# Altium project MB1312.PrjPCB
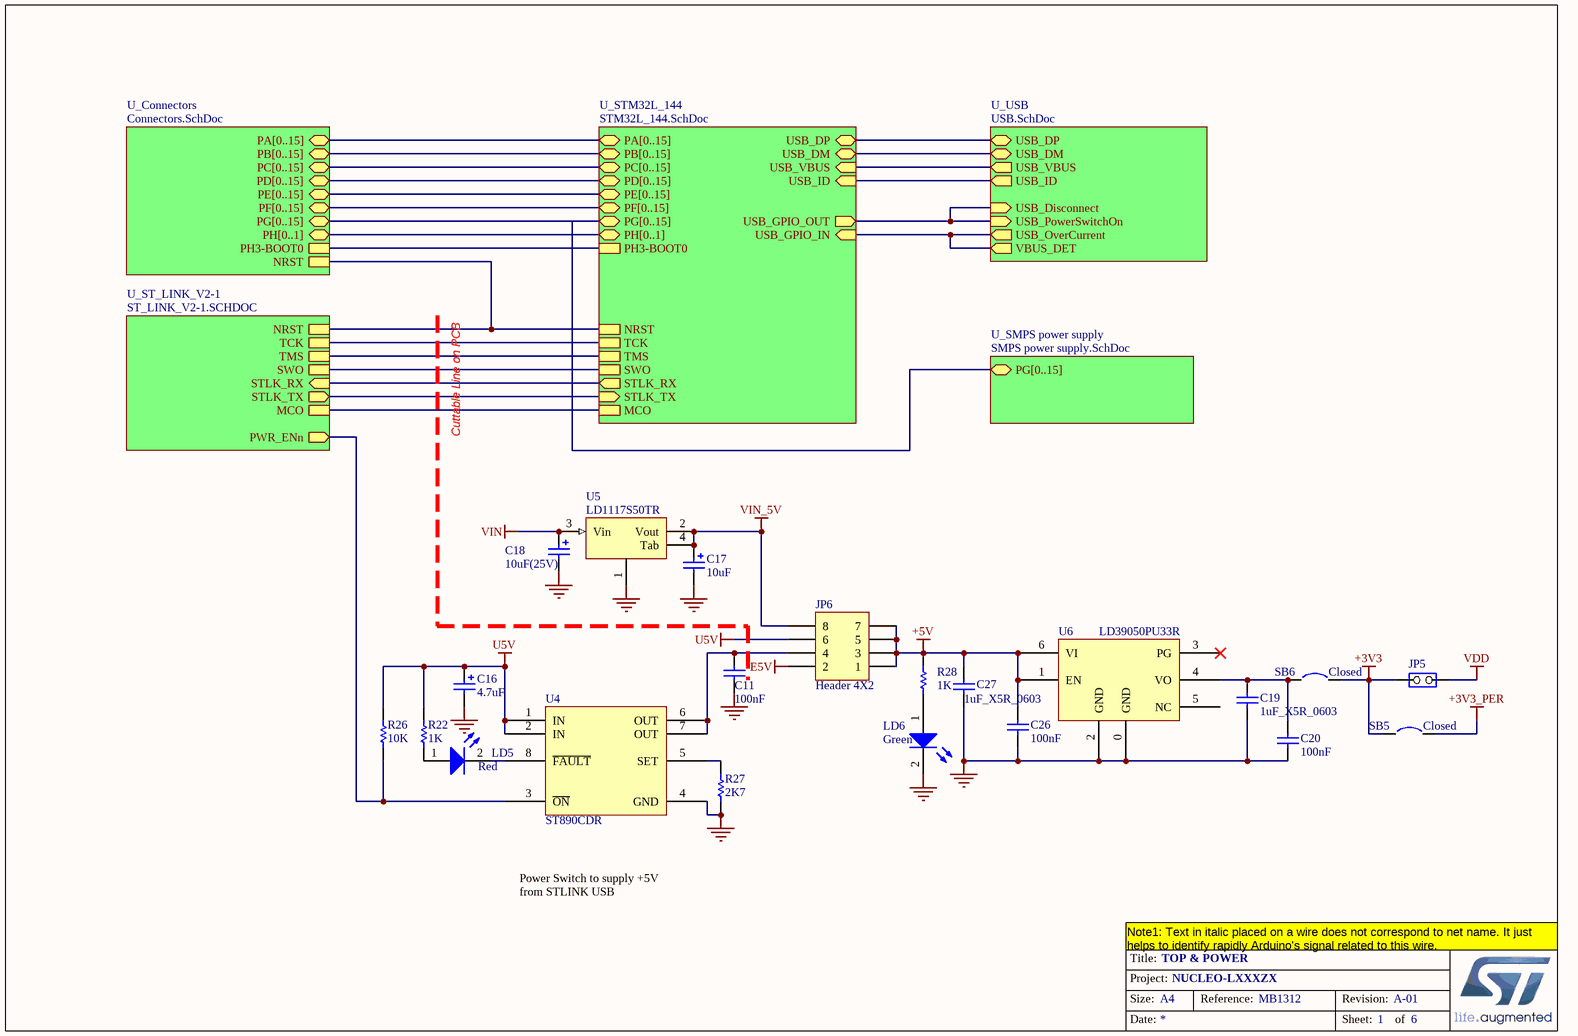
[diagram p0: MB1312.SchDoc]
6 sheets, 297 parts. Net scope: hierarchical (ports join the sheet entries above them; power ports are global).
Sheets:
  MB1312.SchDoc
    U_STM32L_144 = STM32L_144.SchDoc
    U_Connectors = Connectors.SchDoc
    U_ST_LINK_V2-1 = ST_LINK_V2-1.SCHDOC
    U_USB = USB.SchDoc
    U_SMPS power supply = SMPS power supply.SchDoc

## Sheet MB1312.SchDoc: TOP & POWER
size A4; DocumentNumber: MB1312; Revision: A-01; SheetNumber: 1; SheetTotal: 6; Project: NUCLEO-LXXXZX

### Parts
C11  100nF  [0603C]
C16  4.7uF  [TAN-A]
C17  10uF  [TAN-A]
C18  10uF(25V)  [TAN-B]
C19  1uF_X5R_0603  [0603C]
C20  100nF  [0603C]
C26  100nF  [0603C]
C27  1uF_X5R_0603  [0603C]
JP5  (no value)  [HDR_1x2_2R54_V_M_S]
JP6  Header 4X2  [HDR_4x2_2R54_V_M]
LD5  Red  [0603D-R]
LD6  Green  [0603D-G]
R22  1K  [0603R]
R26  10K  [0603R]
R27  2K7  [0603R]
R28  1K  [0603R]
SB5  Closed  [SB_0603]
SB6  Closed  [SB_0603]
U4  ST890CDR  [SOIC8_1R27_4R9X6]
U5  LD1117S50TR  [SOT-223]
U6  LD39050PU33R  [DFN6_0R95_3x3_TP]

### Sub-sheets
U_Connectors = Connectors.SchDoc: PA[0..15] (bidir), PB[0..15] (bidir), PC[0..15] (bidir), NRST, PH3-BOOT0, PD[0..15] (bidir), PE[0..15] (bidir), PF[0..15] (bidir), PG[0..15] (bidir), PH[0..1] (bidir)
U_SMPS power supply = SMPS power supply.SchDoc: PG[0..15] (bidir)
U_ST_LINK_V2-1 = ST_LINK_V2-1.SCHDOC: TMS, TCK, MCO, NRST, STLK_RX (in), STLK_TX (out), SWO, PWR_ENn (out)
U_STM32L_144 = STM32L_144.SchDoc: NRST, MCO, STLK_TX (in), STLK_RX (out), PA[0..15] (bidir), PB[0..15] (bidir), PC[0..15] (bidir), TCK, TMS, SWO, PH3-BOOT0, PD[0..15] (bidir), PE[0..15] (bidir), PF[0..15] (bidir), PG[0..15] (bidir), PH[0..1] (bidir), USB_DM (bidir), USB_DP (bidir), USB_GPIO_OUT (out), USB_GPIO_IN (in), USB_ID (in), USB_VBUS (in)
U_USB = USB.SchDoc: USB_PowerSwitchOn (in), USB_OverCurrent (out), USB_DM (bidir), USB_DP (bidir), USB_ID (out), USB_VBUS (out), USB_Disconnect (in), VBUS_DET (out)

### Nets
+3V3: JP5.1(COMMON) SB5.1 SB6.2
+3V3_PER: SB5.2
+5V: C26.2 C27.1 JP6.1 JP6.3 JP6.5 JP6.7 R28.2 U6.1(EN) U6.6(VI)
E5V: JP6.2
GND: C11.1 C16.2 C17.2 C18.2 C19.2 C20.1 C26.1 C27.2 LD6.2(K) R27.1 U4.4(GND) U5.1 U6.0(GND) U6.2(GND)
U5V: C16.1 JP6.6 R22.1 R26.1 U4.1(IN) U4.2(IN)
VDD: JP5.2(NO)
VIN: C18.1 U5.3(Vin)
VIN_5V: C17.1 JP6.8 U5.2(Vout) U5.4(Tab)
MCO: sheet U_STM32L_144/MCO, sheet U_ST_LINK_V2-1/MCO
NRST: sheet U_STM32L_144/NRST, sheet U_Connectors/NRST, sheet U_ST_LINK_V2-1/NRST
PA13: sheet U_STM32L_144/TMS, sheet U_ST_LINK_V2-1/TMS
PA14: sheet U_STM32L_144/TCK, sheet U_ST_LINK_V2-1/TCK
PB3: sheet U_STM32L_144/SWO, sheet U_ST_LINK_V2-1/SWO
PG6: sheet U_STM32L_144/USB_GPIO_OUT, sheet U_USB/USB_PowerSwitchOn, sheet U_USB/USB_Disconnect
PH3-BOOT0: sheet U_STM32L_144/PH3-BOOT0, sheet U_Connectors/PH3-BOOT0
NetC11_2: C11.2 JP6.4 U4.6(OUT) U4.7(OUT)
NetC19_1: C19.1 C20.2 SB6.1 U6.4(VO)
NetC42_1: sheet U_STM32L_144/USB_VBUS, sheet U_USB/USB_VBUS
NetCN6_1: sheet U_STM32L_144/STLK_RX, sheet U_ST_LINK_V2-1/STLK_RX
NetCN6_2: sheet U_STM32L_144/STLK_TX, sheet U_ST_LINK_V2-1/STLK_TX
NetCN14_2: sheet U_STM32L_144/USB_DM, sheet U_USB/USB_DM
NetCN14_3: sheet U_STM32L_144/USB_DP, sheet U_USB/USB_DP
NetCN14_4: sheet U_STM32L_144/USB_ID, sheet U_USB/USB_ID
NetJP4_1: sheet U_STM32L_144/USB_GPIO_IN, sheet U_USB/USB_OverCurrent, sheet U_USB/VBUS_DET
NetLD5_1: LD5.1(A) R22.2
NetLD5_2: LD5.2(K) U4.8(~{FAULT})
NetLD6_1: LD6.1(A) R28.1
NetR26_2: R26.2 U4.3(~{ON}) ; sheet U_ST_LINK_V2-1/PWR_ENn
NetR27_2: R27.2 U4.5(SET)

Not connected (* = marked no-connect by the designer): U6 3(PG)* 5(NC)

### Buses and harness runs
bus sheet U_Connectors/PA[0..15] = sheet U_STM32L_144/PA[0..15]
bus sheet U_Connectors/PB[0..15] = sheet U_STM32L_144/PB[0..15]
bus sheet U_Connectors/PC[0..15] = sheet U_STM32L_144/PC[0..15]
bus sheet U_Connectors/PD[0..15] = sheet U_STM32L_144/PD[0..15]
bus sheet U_Connectors/PE[0..15] = sheet U_STM32L_144/PE[0..15]
bus sheet U_Connectors/PF[0..15] = sheet U_STM32L_144/PF[0..15]
bus sheet U_Connectors/PG[0..15] = sheet U_SMPS power supply/PG[0..15] = sheet U_STM32L_144/PG[0..15]
bus sheet U_Connectors/PH[0..1] = sheet U_STM32L_144/PH[0..1]

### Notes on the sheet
- Cuttable Line on PCB
- Power Switch to supply +5V from STLINK USB
- Note1: Text in italic placed on a wire does not correspond to net name. It just helps to identify rapidly Arduino's signal related to this wire.

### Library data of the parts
C11 C20 C26 = Capacitor_ST: Capacitor 0402 / 0603 / 0805
C16 = Cap Pol1: Polarized Capacitor (Radial); Value: 100pF; Ordered by: Subcon
C17 C18 = Cap Pol1: Polarized Capacitor (Radial)
C19 C27 = CAP SMD 0603  X5R 1µF 25V 10%: 0603  X5R 1µF; Rated voltage: 25V; Tolerance: 10%
JP5 = JP2
JP6 = Header 4X2: Header, 4-Pin, Dual row
LD5 LD6 = LED2: Typical RED, GREEN, YELLOW, AMBER GaAs LED
R22 = Res1: Resistor; Ordered by: Subcon
R26 = Resistor_ST: Resistor 0402 / 0603 / 0805; Description: Resistor 0402 or 0603 or 0805
R27 R28 = Resistor_ST: Resistor 0402 / 0603 / 0805; Description: Resistor 0402 or 0603 or 0805; Value: 10K
SB5 SB6 = Circuit Breaker_close: Circuit Breaker
U5 = LD1117
U6 = LD39050P

## Sheet STM32L_144.SchDoc: MCU
size A3; DocumentNumber: MB1312; Revision: A-01; SheetNumber: 2; SheetTotal: 6; Project: NUCLEO-LXXXZX
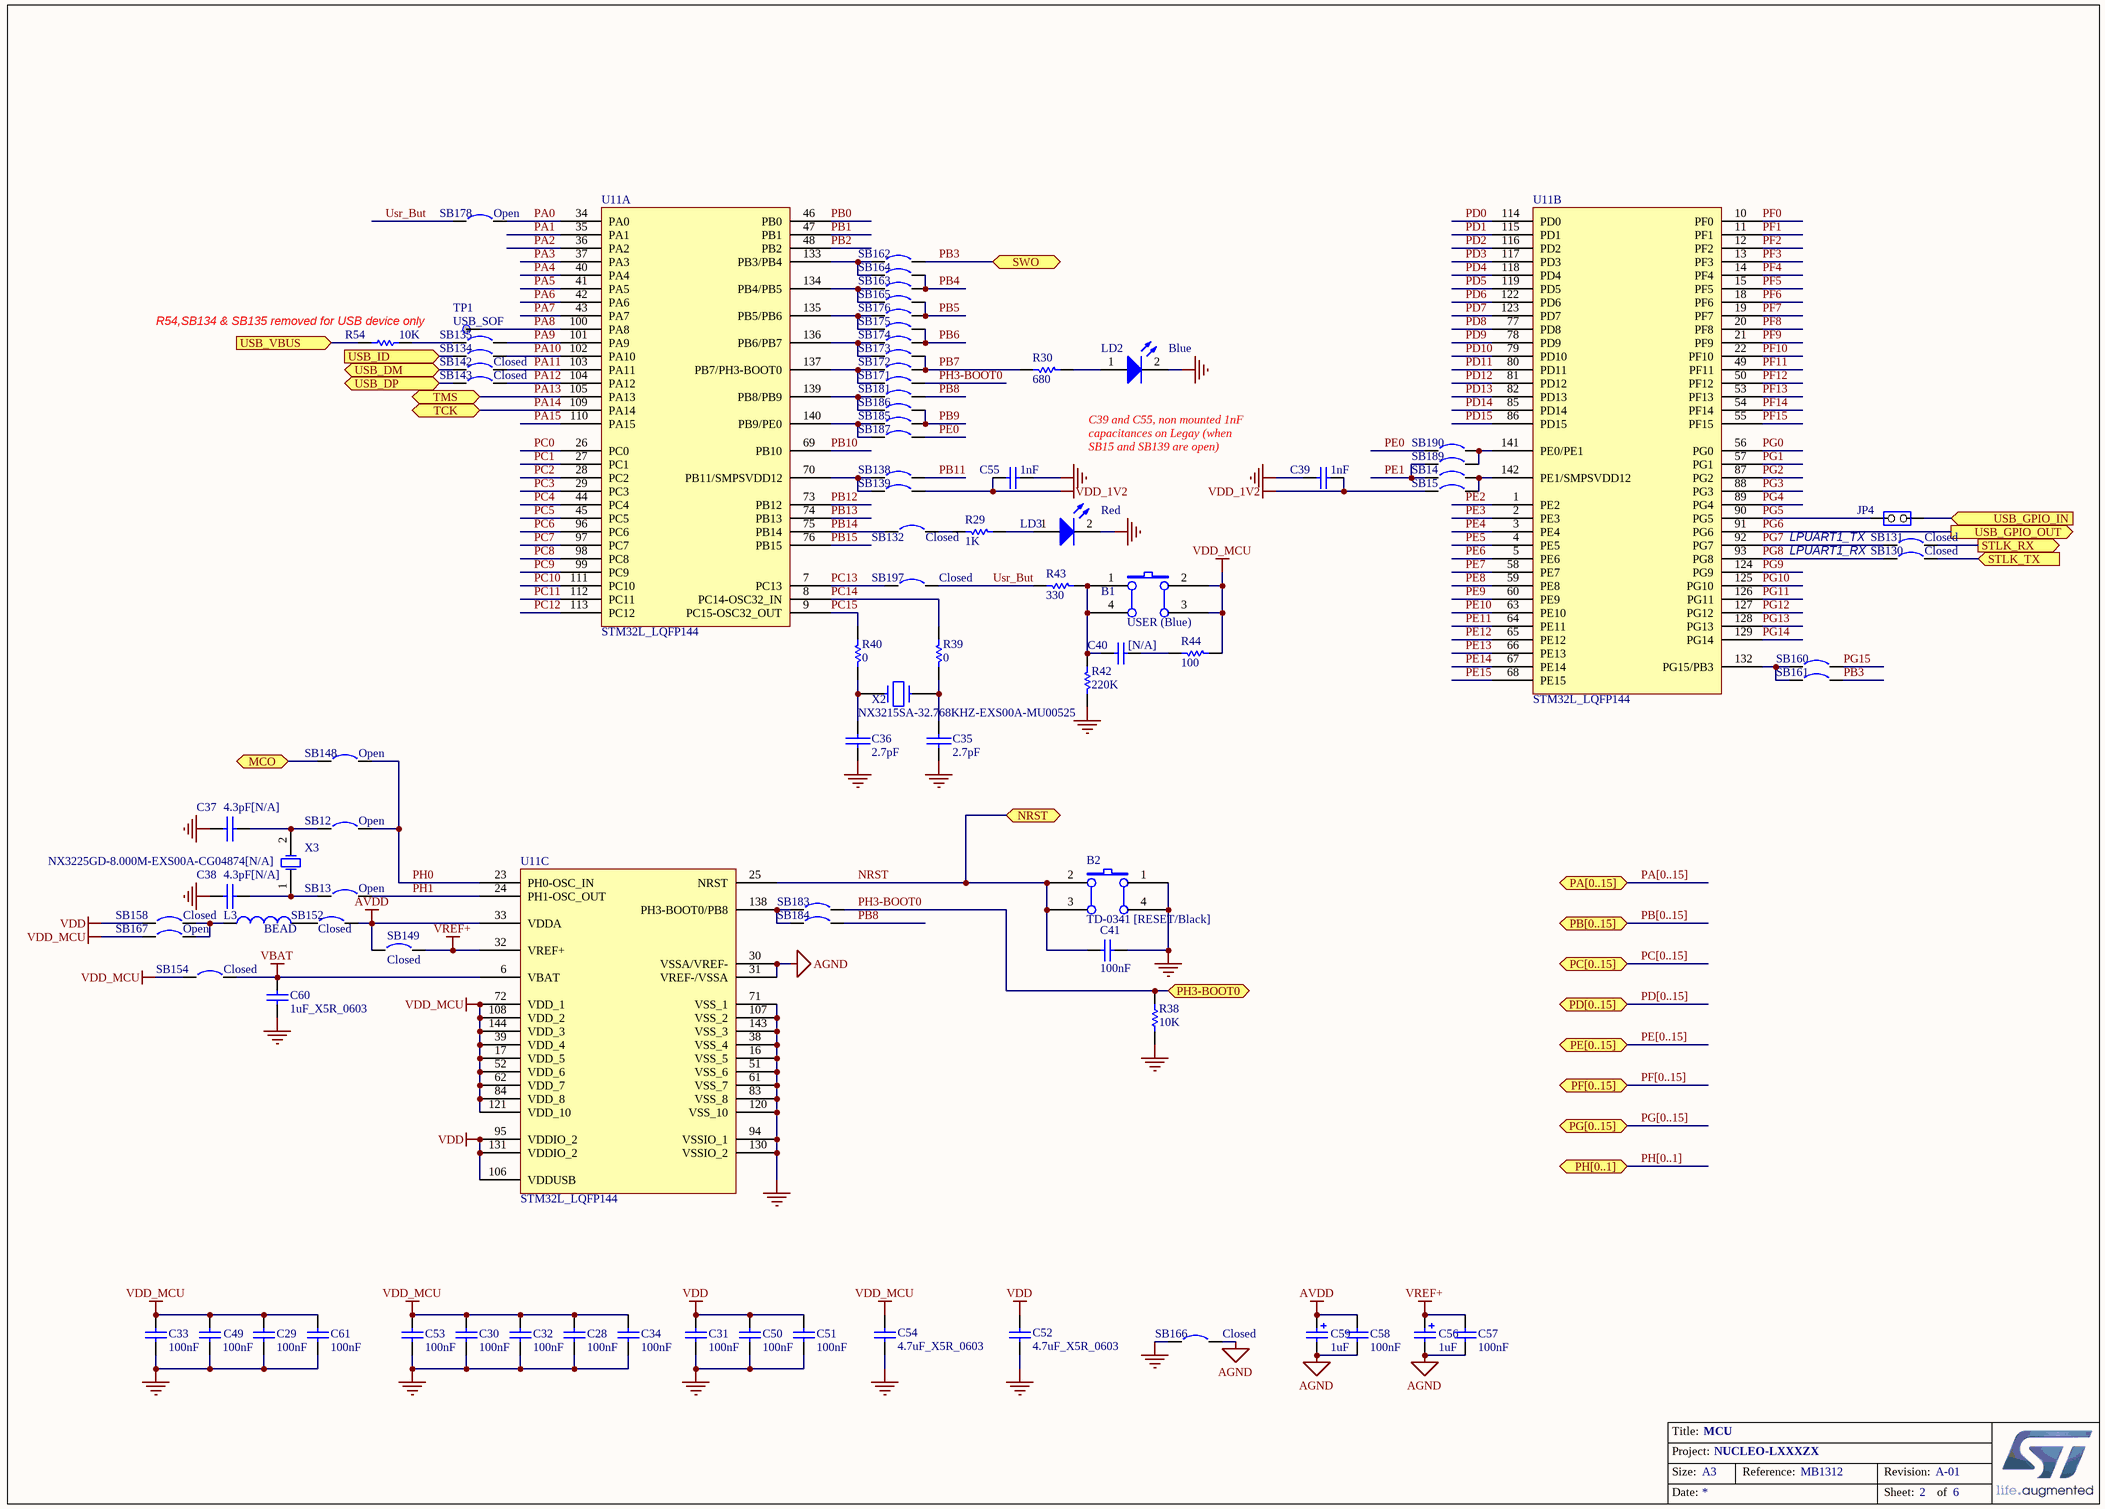
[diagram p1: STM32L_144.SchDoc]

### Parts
B1  USER (Blue)  [PB-6X6mm-Blue]
B2  TD-0341 [RESET/Black]  [PB-6X6mm-Black]
C28  100nF  [0603C]
C29  100nF  [0603C]
C30  100nF  [0603C]
C31  100nF  [0603C]
C32  100nF  [0603C]
C33  100nF  [0603C]
C34  100nF  [0603C]
C35  2.7pF  [0603C]
C36  2.7pF  [0603C]
C37  4.3pF[N/A]  [0603C]
C38  4.3pF[N/A]  [0603C]
C39  1nF  [0603C]
C40  [N/A]  [0603C]
C41  100nF  [0603C]
C49  100nF  [0603C]
C50  100nF  [0603C]
C51  100nF  [0603C]
C52  4.7uF_X5R_0603  [0603C]
C53  100nF  [0603C]
C54  4.7uF_X5R_0603  [0603C]
C55  1nF  [0603C]
C56  value 1uF  [TAN-A]  (hidden comment: TAJA105K016R)
C57  100nF  [0603C]
C58  100nF  [0603C]
C59  value 1uF  [TAN-A]  (hidden comment: TAJA105K016R)
C60  1uF_X5R_0603  [0603C]
C61  100nF  [0603C]
JP4  (no value)  [HDR_1x2_2R54_V_M_S]
L3  BEAD  [0603L]
LD2  Blue  [0603D-B]
LD3  Red  [0603D-R]
R29  1K  [0603R]
R30  680  [0603R]
R38  10K  [0603R]
R39  0  [0603R]
R40  0  [0603R]
R42  220K  [0603R]
R43  330  [0603R]
R44  100  [0603R]
R54  10K  [0603R]
SB12  Open  [SB_0603]
SB13  Open  [SB_0603]
SB14  Circuit Breaker  [SB_0603]  (value not drawn)
SB15  Circuit Breaker  [SB_0603]  (value not drawn)
SB130  Closed  [SB_0603]
SB131  Closed  [SB_0603]
SB132  Closed  [SB_0603]
SB134  Circuit Breaker  [SB_0603]  (value not drawn)
SB135  Circuit Breaker  [SB_0603]  (value not drawn)
SB138  Circuit Breaker  [SB_0603]  (value not drawn)
SB139  Circuit Breaker  [SB_0603]  (value not drawn)
SB142  Closed  [SB_0603]
SB143  Closed  [SB_0603]
SB148  Open  [SB_0603]
SB149  Closed  [SB_0603]
SB152  Closed  [SB_0603]
SB154  Closed  [SB_0603]
SB158  Closed  [SB_0603]
SB160  Circuit Breaker  [SB_0603]  (value not drawn)
SB161  Circuit Breaker  [SB_0603]  (value not drawn)
SB162  Circuit Breaker  [SB_0603]  (value not drawn)
SB163  Circuit Breaker  [SB_0603]  (value not drawn)
SB164  Circuit Breaker  [SB_0603]  (value not drawn)
SB165  Circuit Breaker  [SB_0603]  (value not drawn)
SB166  Closed  [SB_0603]
SB167  Open  [SB_0603]
SB171  Circuit Breaker  [SB_0603]  (value not drawn)
SB172  Circuit Breaker  [SB_0603]  (value not drawn)
SB173  Circuit Breaker  [SB_0603]  (value not drawn)
SB174  Circuit Breaker  [SB_0603]  (value not drawn)
SB175  Circuit Breaker  [SB_0603]  (value not drawn)
SB176  Circuit Breaker  [SB_0603]  (value not drawn)
SB178  Open  [SB_0603]
SB181  Circuit Breaker  [SB_0603]  (value not drawn)
SB183  Circuit Breaker  [SB_0603]  (value not drawn)
SB184  Circuit Breaker  [SB_0603]  (value not drawn)
SB185  Circuit Breaker  [SB_0603]  (value not drawn)
SB186  Circuit Breaker  [SB_0603]  (value not drawn)
SB187  Circuit Breaker  [SB_0603]  (value not drawn)
SB189  Circuit Breaker  [SB_0603]  (value not drawn)
SB190  Circuit Breaker  [SB_0603]  (value not drawn)
SB197  Closed  [SB_0603]
TP1  USB_SOF  [TP]
U11  STM32L_LQFP144  [LQFP144_0R5_SKT]  (parts A,B,C of 3)
X2  NX3215SA-32.768KHZ-EXS00A-MU00525  [XTAL_2SM_3R2X1R5]
X3  NX3225GD-8.000M-EXS00A-CG04874[N/A]  [OSC_2SM_3R2x2R5]

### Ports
MCO, NRST, PA[0..15] (bidir), PB[0..15] (bidir), PC[0..15] (bidir), PD[0..15] (bidir), PE[0..15] (bidir), PF[0..15] (bidir), PG[0..15] (bidir), PH3-BOOT0, PH[0..1] (bidir), STLK_RX (out), STLK_TX (in), SWO, TCK, TMS, USB_DM (bidir), USB_DP (bidir), USB_GPIO_IN (in), USB_GPIO_OUT (out), USB_ID (in), USB_VBUS (in)

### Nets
AGND: C56.2 C57.2 C58.2 C59.2 SB166.2 U11.30(VSSA/VREF-) U11.31(VREF-/VSSA)
AVDD: C58.1 C59.1 SB149.1 SB152.2 U11.33(VDDA)
GND: B2.1(A0) B2.4(A1) C28.2 C29.2 C30.2 C31.2 C32.2 C33.2 C34.2 C35.2 C36.2 C37.2 C38.2 C39.1 C41.1 C49.2 C50.2 C51.2 C52.2 C53.2 C54.2 C55.1 C60.2 C61.2 LD2.2(K) LD3.2(K) R38.2 R42.2 SB166.1 U11.16(VSS_5) U11.38(VSS_4) U11.51(VSS_6) U11.61(VSS_7) U11.71(VSS_1) U11.83(VSS_8) U11.94(VSSIO_1) U11.107(VSS_2) U11.120(VSS_10) U11.130(VSSIO_2) U11.143(VSS_3)
VBAT: C60.1 SB154.2 U11.6(VBAT)
VDD: C31.1 C50.1 C51.1 C52.1 SB158.1 U11.95(VDDIO_2) U11.106(VDDUSB) U11.131(VDDIO_2)
VDD_1V2: C39.2 C55.2 SB15.2 SB139.2
VDD_MCU: B1.2(B0) B1.3(B1) C28.1 C29.1 C30.1 C32.1 C33.1 C34.1 C49.1 C53.1 C54.1 C61.1 R44.1 SB154.1 SB167.1 U11.17(VDD_5) U11.39(VDD_4) U11.52(VDD_6) U11.62(VDD_7) U11.72(VDD_1) U11.84(VDD_8) U11.108(VDD_2) U11.121(VDD_10) U11.144(VDD_3)
VREF+: C56.1 C57.1 SB149.2 U11.32(VREF+)
MCO: SB148.2 ; port MCO
NRST: B2.2(B0) B2.3(B1) C41.2 U11.25(NRST) ; port NRST
PA0: SB178.2 U11.34(PA0)
PA1: U11.35(PA1)
PA2: U11.36(PA2)
PA3: U11.37(PA3)
PA4: U11.40(PA4)
PA5: U11.41(PA5)
PA6: U11.42(PA6)
PA7: U11.43(PA7)
PA8: TP1.1 U11.100(PA8)
PA9: SB135.2 U11.101(PA9)
PA10: SB134.2 U11.102(PA10)
PA11: SB142.2 U11.103(PA11)
PA12: SB143.2 U11.104(PA12)
PA13: U11.105(PA13) ; port TMS
PA14: U11.109(PA14) ; port TCK
PA15: U11.110(PA15)
PB0: U11.46(PB0)
PB1: U11.47(PB1)
PB2: U11.48(PB2)
PB3: SB161.2 SB162.2 ; port SWO
PB4: SB163.2 SB164.2
PB5: SB165.2 SB176.2
PB6: SB174.2 SB175.2
PB7: R30.1 SB172.2 SB173.2
PB8: SB181.2 SB184.2
PB9: SB185.2 SB186.2
PB10: U11.69(PB10)
PB11: SB138.2
PB12: U11.73(PB12)
PB13: U11.74(PB13)
PB14: SB132.1 U11.75(PB14)
PB15: U11.76(PB15)
PC0: U11.26(PC0)
PC1: U11.27(PC1)
PC2: U11.28(PC2)
PC3: U11.29(PC3)
PC4: U11.44(PC4)
PC5: U11.45(PC5)
PC6: U11.96(PC6)
PC7: U11.97(PC7)
PC8: U11.98(PC8)
PC9: U11.99(PC9)
PC10: U11.111(PC10)
PC11: U11.112(PC11)
PC12: U11.113(PC12)
PC13: SB197.1 U11.7(PC13)
PC14: R39.2 U11.8(PC14-OSC32_IN)
PC15: R40.2 U11.9(PC15-OSC32_OUT)
PD0: U11.114(PD0)
PD1: U11.115(PD1)
PD2: U11.116(PD2)
PD3: U11.117(PD3)
PD4: U11.118(PD4)
PD5: U11.119(PD5)
PD6: U11.122(PD6)
PD7: U11.123(PD7)
PD8: U11.77(PD8)
PD9: U11.78(PD9)
PD10: U11.79(PD10)
PD11: U11.80(PD11)
PD12: U11.81(PD12)
PD13: U11.82(PD13)
PD14: U11.85(PD14)
PD15: U11.86(PD15)
PE0: SB187.2 SB190.1
PE1: SB14.1 SB189.1
PE2: U11.1(PE2)
PE3: U11.2(PE3)
PE4: U11.3(PE4)
PE5: U11.4(PE5)
PE6: U11.5(PE6)
PE7: U11.58(PE7)
PE8: U11.59(PE8)
PE9: U11.60(PE9)
PE10: U11.63(PE10)
PE11: U11.64(PE11)
PE12: U11.65(PE12)
PE13: U11.66(PE13)
PE14: U11.67(PE14)
PE15: U11.68(PE15)
PF0: U11.10(PF0)
PF1: U11.11(PF1)
PF2: U11.12(PF2)
PF3: U11.13(PF3)
PF4: U11.14(PF4)
PF5: U11.15(PF5)
PF6: U11.18(PF6)
PF7: U11.19(PF7)
PF8: U11.20(PF8)
PF9: U11.21(PF9)
PF10: U11.22(PF10)
PF11: U11.49(PF11)
PF12: U11.50(PF12)
PF13: U11.53(PF13)
PF14: U11.54(PF14)
PF15: U11.55(PF15)
PG0: U11.56(PG0)
PG1: U11.57(PG1)
PG2: U11.87(PG2)
PG3: U11.88(PG3)
PG4: U11.89(PG4)
PG5: JP4.2(NO) U11.90(PG5)
PG6: U11.91(PG6) ; port USB_GPIO_OUT
PG7: SB131.1 U11.92(PG7)
PG8: SB130.1 U11.93(PG8)
PG9: U11.124(PG9)
PG10: U11.125(PG10)
PG11: U11.126(PG11)
PG12: U11.127(PG12)
PG13: U11.128(PG13)
PG14: U11.129(PG14)
PG15: SB160.2
PH0: SB12.2 SB148.1 U11.23(PH0-OSC_IN)
PH1: SB13.2 U11.24(PH1-OSC_OUT)
PH3-BOOT0: R38.1 SB171.2 SB183.2 ; port PH3-BOOT0
Usr_But: R43.2 SB178.1 SB197.2
NetB1_1: B1.1(A0) B1.4(A1) C40.2 R42.1 R43.1
NetC35_1: C35.1 R39.1 X2.2
NetC36_1: C36.1 R40.1 X2.1
NetC37_1: C37.1 SB12.1 X3.2(OSC2)
NetC38_1: C38.1 SB13.1 X3.1(OSC1)
NetC40_1: C40.1 R44.2
NetC42_1: R54.1 ; port USB_VBUS
NetCN6_1: SB131.2 ; port STLK_RX
NetCN6_2: SB130.2 ; port STLK_TX
NetCN14_2: SB142.1 ; port USB_DM
NetCN14_3: SB143.1 ; port USB_DP
NetCN14_4: SB134.1 ; port USB_ID
NetJP4_1: JP4.1(COMMON) ; port USB_GPIO_IN
NetL3_1: L3.1 SB158.2 SB167.2
NetL3_2: L3.2 SB152.1
NetLD2_1: LD2.1(A) R30.2
NetLD3_1: LD3.1(A) R29.2
NetR29_1: R29.1 SB132.2
NetR54_2: R54.2 SB135.1
NetSB14_2: SB14.2 SB15.1 U11.142(PE1/SMPSVDD12)
NetSB138_1: SB138.1 SB139.1 U11.70(PB11/SMPSVDD12)
NetSB160_1: SB160.1 SB161.1 U11.132(PG15/PB3)
NetSB162_1: SB162.1 SB164.1 U11.133(PB3/PB4)
NetSB163_1: SB163.1 SB165.1 U11.134(PB4/PB5)
NetSB171_1: SB171.1 SB172.1 U11.137(PB7/PH3-BOOT0)
NetSB173_1: SB173.1 SB174.1 U11.136(PB6/PB7)
NetSB175_1: SB175.1 SB176.1 U11.135(PB5/PB6)
NetSB181_1: SB181.1 SB186.1 U11.139(PB8/PB9)
NetSB183_1: SB183.1 SB184.1 U11.138(PH3-BOOT0/PB8)
NetSB185_1: SB185.1 SB187.1 U11.140(PB9/PE0)
NetSB189_2: SB189.2 SB190.2 U11.141(PE0/PE1)

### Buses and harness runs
bus PA[0..15] = port PA[0..15]
bus PB[0..15] = port PB[0..15]
bus PC[0..15] = port PC[0..15]
bus PD[0..15] = port PD[0..15]
bus PE[0..15] = port PE[0..15]
bus PF[0..15] = port PF[0..15]
bus PG[0..15] = port PG[0..15]
bus PH[0..1] = port PH[0..1]

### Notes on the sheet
- (near R54) R54,SB134 & SB135 removed for USB device only
- C39 and C55, non mounted 1nF capacitances on Legay (when SB15 and SB139 are open)
- LPUART1_TX
- LPUART1_RX

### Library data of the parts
B1 B2 = SW PUSHBUTTON: SE PUSHBUTTON
C28-C34 C39 C49-C51 C53 C55 C57 C58 C61 = Cap: Capacitor; Value: 10nF
C35-C38 = CAP: Capacitor
C40 C41 = CAP: Capacitor; Value: 100pF
C52 C54 = CAP SMD 0603  X5R 1µF 25V 10%: 0603  X5R 4.7uF; Value: 1µF; Rated voltage: 25V; Tolerance: 10%
C56 C59 = Cap Pol1: Tan Capacitor,1uF,10%,16V,Tan-A,TAJA105K016R; Manuf_1: AVX; Ordered by: Subcon; ECCN_US/EU: NA
C60 = CAP SMD 0603  X5R 1µF 25V 10%: as C19 on sheet MB1312
JP4 = JP2
L3 = Inductor: Value: 100uH
LD2 LD3 = LED2: as LD5 on sheet MB1312
R29 = Res1: Resistor
R30 R39 R40 R43 R44 = Res1: Resistor; Value: 1K
R38 R42 = res1: Resistor; Value: 1K
R54 = Resistor_ST: Resistor 0402 / 0603 / 0805
SB12 SB13 SB148 SB167 SB178 = Circuit Breaker
SB14 SB15 SB134 SB135 SB138 SB139 SB160-SB165 SB171-SB176 SB181 SB183-SB187 SB189 SB190 = Circuit Breaker: Solder: NO
SB130-SB132 SB142 SB143 SB149 SB152 SB154 SB158 SB166 SB197 = Circuit Breaker_close: Circuit Breaker
TP1 = TP
X2 = CRYSTAL_32K: Crystal
X3 = XTAL: Crystal Oscillator

## Sheet Connectors.SchDoc: Extension connectors
size A3; DocumentNumber: MB1312; Revision: A-01; SheetNumber: 5; SheetTotal: 6; Project: NUCLEO-LXXXZX
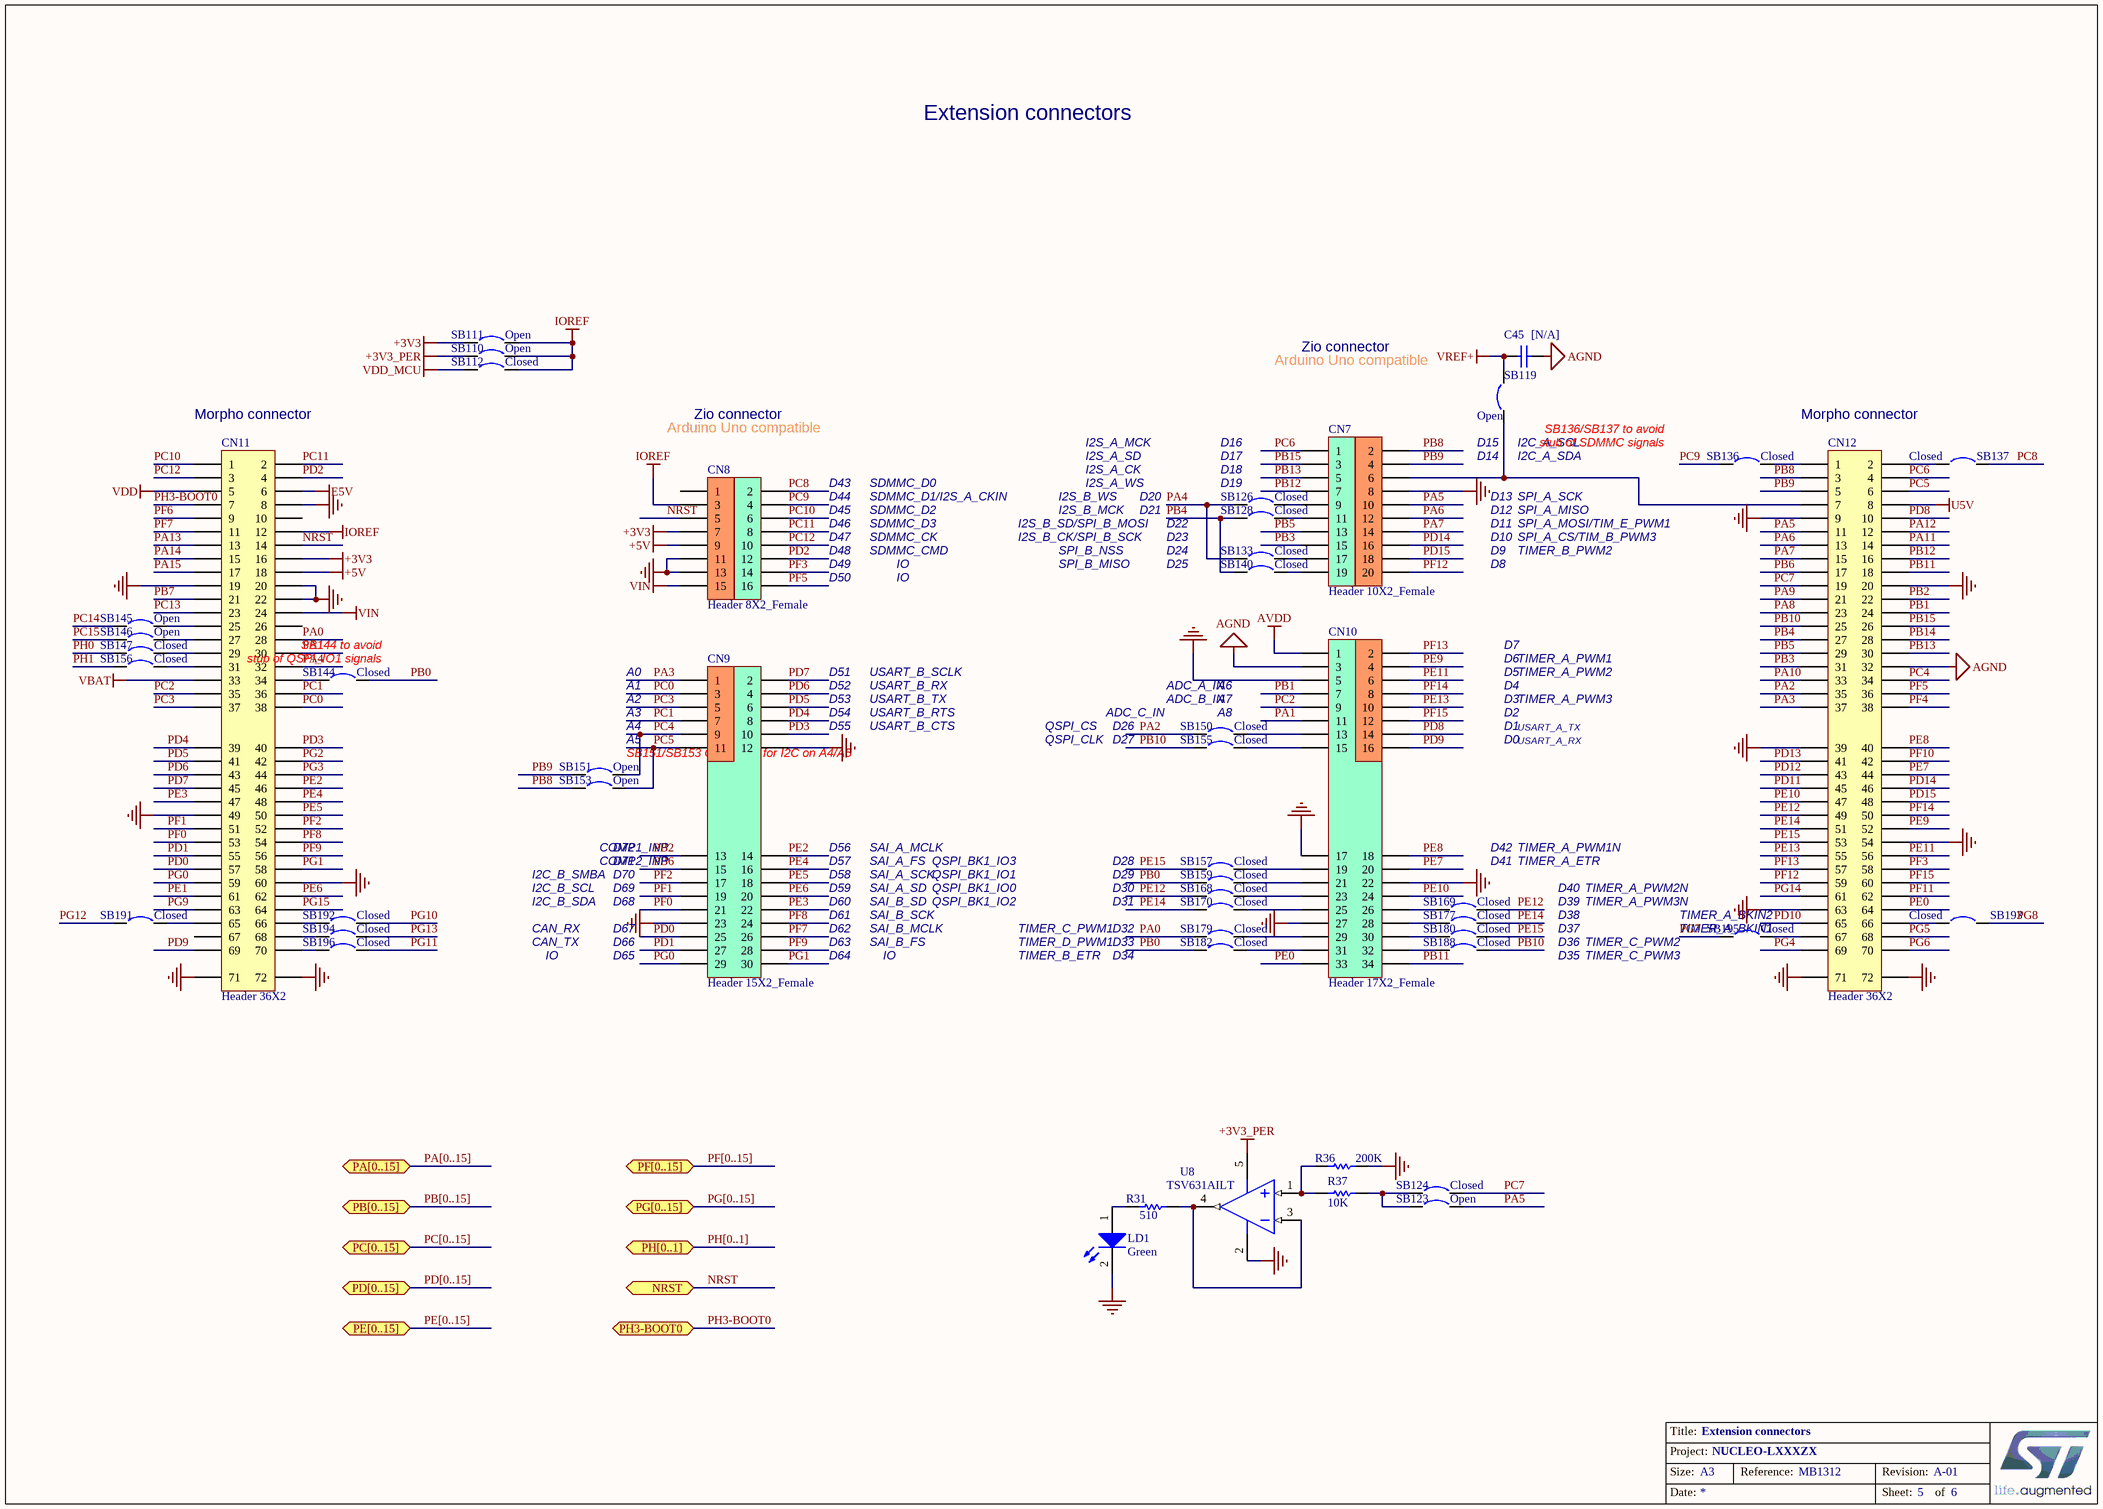
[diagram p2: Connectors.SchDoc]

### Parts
C45  [N/A]  [0603C]
CN7  Header 10X2_Female  [HDR_10x2_2R54_V_F]
CN8  Header 8X2_Female  [HDR_8x2_2R54_V_F]
CN9  Header 15X2_Female  [HDR_15x2_2R54_V_F]
CN10  Header 17X2_Female  [HDR_17x2_2R54_V_F]
CN11  Header 36X2  [HDR_2x36_2R54_V_M]
CN12  Header 36X2  [HDR_2x36_2R54_V_M]
LD1  Green  [0603D-G]
R31  510  [0603R]
R36  200K  [0603R]
R37  10K  [0603R]
SB110  Open  [SB_0603]
SB111  Open  [SB_0603]
SB112  Closed  [SB_0603]
SB119  Open  [SB_0603]
SB123  Open  [SB_0603]
SB124  Closed  [SB_0603]
SB126  Closed  [SB_0603]
SB128  Closed  [SB_0603]
SB133  Closed  [SB_0603]
SB136  Closed  [SB_0603]
SB137  Closed  [SB_0603]
SB140  Closed  [SB_0603]
SB144  Closed  [SB_0603]
SB145  Open  [SB_0603]
SB146  Open  [SB_0603]
SB147  Closed  [SB_0603]
SB150  Closed  [SB_0603]
SB151  Open  [SB_0603]
SB153  Open  [SB_0603]
SB155  Closed  [SB_0603]
SB156  Closed  [SB_0603]
SB157  Closed  [SB_0603]
SB159  Closed  [SB_0603]
SB168  Closed  [SB_0603]
SB169  Closed  [SB_0603]
SB170  Closed  [SB_0603]
SB177  Closed  [SB_0603]
SB179  Closed  [SB_0603]
SB180  Closed  [SB_0603]
SB182  Closed  [SB_0603]
SB188  Closed  [SB_0603]
SB191  Closed  [SB_0603]
SB192  Closed  [SB_0603]
SB193  Closed  [SB_0603]
SB194  Closed  [SB_0603]
SB195  Closed  [SB_0603]
SB196  Closed  [SB_0603]
U8  TSV631AILT  [SOT-23-5L]

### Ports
NRST, PA[0..15] (bidir), PB[0..15] (bidir), PC[0..15] (bidir), PD[0..15] (bidir), PE[0..15] (bidir), PF[0..15] (bidir), PG[0..15] (bidir), PH3-BOOT0, PH[0..1] (bidir)

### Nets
+3V3: CN8.7 CN11.16 SB111.1
+3V3_PER: SB110.1 U8.5(VCC)
+5V: CN8.9 CN11.18
AGND: C45.2 CN10.3 CN12.32
AVDD: CN10.1
E5V: CN11.6
GND: CN7.8 CN8.11 CN8.13 CN9.12 CN9.23 CN10.5 CN10.17 CN10.22 CN10.27 CN11.8 CN11.19 CN11.20 CN11.22 CN11.49 CN11.60 CN11.71 CN11.72 CN12.9 CN12.20 CN12.39 CN12.54 CN12.63 CN12.71 CN12.72 LD1.2(K) R36.2 U8.2(VDD)
IOREF: CN8.3 CN11.12 SB110.2 SB111.2 SB112.2
U5V: CN12.8
VBAT: CN11.33
VDD: CN11.5
VDD_MCU: SB112.1
VIN: CN8.15 CN11.24
VREF+: C45.1 SB119.1
NRST: CN8.5 CN11.14 ; port NRST
PA0: CN11.28 SB179.1
PA1: CN10.11 CN11.30
PA2: CN12.35 SB150.1
PA3: CN9.1 CN12.37
PA4: CN11.32 SB126.1 SB133.1
PA5: CN7.10 CN12.11 SB123.2
PA6: CN7.12 CN12.13
PA7: CN7.14 CN12.15
PA8: CN12.23
PA9: CN12.21
PA10: CN12.33
PA11: CN12.14
PA12: CN12.12
PA13: CN11.13
PA14: CN11.15
PA15: CN11.17
PB0: SB144.2 SB159.1 SB182.1
PB1: CN10.7 CN12.24
PB2: CN9.13 CN12.22
PB3: CN7.15 CN12.31
PB4: CN12.27 SB128.1 SB140.1
PB5: CN7.13 CN12.29
PB6: CN9.15 CN12.17
PB7: CN11.21
PB8: CN7.2 CN12.3 SB153.2
PB9: CN7.4 CN12.5 SB151.2
PB10: CN12.25 SB155.1 SB188.2
PB11: CN10.34 CN12.18
PB12: CN7.7 CN12.16
PB13: CN7.5 CN12.30
PB14: CN12.28
PB15: CN7.3 CN12.26
PC0: CN9.3 CN11.38
PC1: CN9.7 CN11.36
PC2: CN10.9 CN11.35
PC3: CN9.5 CN11.37
PC4: CN9.9 CN12.34 SB151.1
PC5: CN9.11 CN12.6 SB153.1
PC6: CN7.1 CN12.4
PC7: CN12.19 SB124.1
PC8: CN8.2 SB137.1
PC9: CN8.4 SB136.1
PC10: CN8.6 CN11.1
PC11: CN8.8 CN11.2
PC12: CN8.10 CN11.3
PC13: CN11.23
PC14: SB145.1
PC15: SB146.1
PD0: CN9.25 CN11.57
PD1: CN9.27 CN11.55
PD2: CN8.12 CN11.4
PD3: CN9.10 CN11.40
PD4: CN9.8 CN11.39
PD5: CN9.6 CN11.41
PD6: CN9.4 CN11.43
PD7: CN9.2 CN11.45
PD8: CN10.14 CN12.10
PD9: CN10.16 CN11.69
PD10: CN12.65
PD11: CN12.45
PD12: CN12.43
PD13: CN12.41
PD14: CN7.16 CN12.46
PD15: CN7.18 CN12.48
PE0: CN10.33 CN12.64
PE1: CN11.61
PE2: CN9.14 CN11.46
PE3: CN9.22 CN11.47
PE4: CN9.16 CN11.48
PE5: CN9.18 CN11.50
PE6: CN9.20 CN11.62
PE7: CN10.20 CN12.44
PE8: CN10.18 CN12.40
PE9: CN10.4 CN12.52
PE10: CN10.24 CN12.47
PE11: CN10.6 CN12.56
PE12: CN12.49 SB168.1 SB169.2
PE13: CN10.10 CN12.55
PE14: CN12.51 SB170.1 SB177.2
PE15: CN12.53 SB157.1 SB180.2
PF0: CN9.21 CN11.53
PF1: CN9.19 CN11.51
PF2: CN9.17 CN11.52
PF3: CN8.14 CN12.58
PF4: CN12.38
PF5: CN8.16 CN12.36
PF6: CN11.9
PF7: CN9.26 CN11.11
PF8: CN9.24 CN11.54
PF9: CN9.28 CN11.56
PF10: CN12.42
PF11: CN12.62
PF12: CN7.20 CN12.59
PF13: CN10.2 CN12.57
PF14: CN10.8 CN12.50
PF15: CN10.12 CN12.60
PG0: CN9.29 CN11.59
PG1: CN9.30 CN11.58
PG2: CN11.42
PG3: CN11.44
PG4: CN12.69
PG5: CN12.68
PG6: CN12.70
PG7: SB195.1
PG8: SB193.2
PG9: CN11.63
PG10: SB192.2
PG11: SB196.2
PG12: SB191.1
PG13: SB194.2
PG14: CN12.61
PG15: CN11.64
PH0: SB147.1
PH1: SB156.1
PH3-BOOT0: CN11.7 ; port PH3-BOOT0
NetCN7_6: CN7.6 CN12.7 SB119.2
NetCN7_9: CN7.9 SB126.2
NetCN7_11: CN7.11 SB128.2
NetCN7_17: CN7.17 SB133.2
NetCN7_19: CN7.19 SB140.2
NetCN10_13: CN10.13 SB150.2
NetCN10_15: CN10.15 SB155.2
NetCN10_19: CN10.19 SB157.2
NetCN10_21: CN10.21 SB159.2
NetCN10_23: CN10.23 SB168.2
NetCN10_25: CN10.25 SB170.2
NetCN10_26: CN10.26 SB169.1
NetCN10_28: CN10.28 SB177.1
NetCN10_29: CN10.29 SB179.2
NetCN10_30: CN10.30 SB180.1
NetCN10_31: CN10.31 SB182.2
NetCN10_32: CN10.32 SB188.1
NetCN11_25: CN11.25 SB145.2
NetCN11_27: CN11.27 SB146.2
NetCN11_29: CN11.29 SB147.2
NetCN11_31: CN11.31 SB156.2
NetCN11_34: CN11.34 SB144.1
NetCN11_65: CN11.65 SB191.2
NetCN11_66: CN11.66 SB192.1
NetCN11_68: CN11.68 SB194.1
NetCN11_70: CN11.70 SB196.1
NetCN12_1: CN12.1 SB136.2
NetCN12_2: CN12.2 SB137.2
NetCN12_66: CN12.66 SB193.1
NetCN12_67: CN12.67 SB195.2
NetLD1_1: LD1.1(A) R31.2
NetR31_1: R31.1 U8.3(IN-) U8.4(OUT)
NetR36_1: R36.1 R37.1 U8.1(IN+)
NetR37_2: R37.2 SB123.1 SB124.2

Not connected (* = marked no-connect by the designer): CN8 1; CN11 10 26 67

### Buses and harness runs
bus PA[0..15] = port PA[0..15]
bus PB[0..15] = port PB[0..15]
bus PC[0..15] = port PC[0..15]
bus PD[0..15] = port PD[0..15]
bus PE[0..15] = port PE[0..15]
bus PF[0..15] = port PF[0..15]
bus PG[0..15] = port PG[0..15]
bus PH[0..1] = port PH[0..1]

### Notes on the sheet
- Extension connectors
- Arduino Uno compatible
- Zio connector
- (near CN11) Morpho connector
- I2S_A_MCK
- D16
- (near SB119) D15
- (near SB119) I2C_A_SCL
- (near SB136) SB136/SB137 to avoid
- (near SB136) stub of SDMMC signals
- Morpho connector
- D43
- D44
- D45
- SDMMC_D0
- SDMMC_D1/I2S_A_CKIN
- SDMMC_D2
- I2S_B_WS
- I2S_B_MCK
- I2S_A_SD
- I2S_A_CK
- I2S_A_WS
- D20
- D21
- D17
- D18
- (near SB126) D19
- (near SB119) D14
- D13
- D12
- SPI_A_SCK
- SPI_A_MISO
- (near SB119) I2C_A_SDA
- D46
- D47
- D48
- D49
- D50
- SDMMC_CK
- SDMMC_CMD
- SDMMC_D3
- IO
- I2S_B_SD/SPI_B_MOSI
- I2S_B_CK/SPI_B_SCK
- SPI_B_MISO
- SPI_B_NSS
- D22
- D23
- D24
- D25
- D8
- D9
- D10
- D11
- TIMER_B_PWM2
- SPI_A_CS/TIM_B_PWM3
- SPI_A_MOSI/TIM_E_PWM1
- (near SB144) SB144 to avoid
- D7
- (near SB144) stub of QSPI_IO1 signals
- A0
- A1
- A2
- A3
- D51
- D52
- D53
- D54
- USART_B_TX
- USART_B_RX
- USART_B_SCLK
- USART_B_RTS
- ADC_A_IN
- ADC_B_IN
- (near SB150) ADC_C_IN
- A6
- A7
- (near SB150) A8
- D2
- D4
- D3
- D5
- D6
- TIMER_A_PWM1
- TIMER_A_PWM2
- TIMER_A_PWM3
- A4
- A5
- (near SB151) SB151/SB153 Close only for I2C on A4/A5
- D55
- USART_B_CTS
- QSPI_CLK
- QSPI_CS
- D26
- D27
- D0
- D1
- USART_A_TX
- USART_A_RX
- COMP1_INP
- D72
- D56
- SAI_A_MCLK
- D42
- TIMER_A_PWM1N
- I2C_B_SCL
- I2C_B_SDA
- I2C_B_SMBA
- COMP2_INP
- D71
- D70
- D69
- D68
- D57
- D58
- D59
- D60
- D61
- SAI_A_SD
- SAI_A_SCK
- SAI_A_FS
- SAI_B_SD
- SAI_B_SCK
- QSPI_BK1_IO0
- QSPI_BK1_IO2
- QSPI_BK1_IO1
- QSPI_BK1_IO3
- D28
- D29
- D30
- D31
- D41
- TIMER_A_ETR
- D38
- D39
- D40
- TIMER_A_PWM2N
- TIMER_A_PWM3N
- TIMER_A_BKIN2
- CAN_TX
- CAN_RX
- D67
- D66
- D65
- D62
- D63
- D64
- SAI_B_FS
- SAI_B_MCLK
- TIMER_D_PWM1
- TIMER_B_ETR
- TIMER_C_PWM1
- D32
- D33
- D34
- D35
- D36
- D37
- TIMER_C_PWM2
- TIMER_C_PWM3
- TIMER_A_BKIN1

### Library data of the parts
C45 = Cap: Capacitor,100nF,10%,16V,X7R,0603,YAGEO; Manuf_Part_1: CC0603KRX7R7BB104; Ordered by: Subcon
CN7 = Header 10X2_Female: Header, 10-Pin, Dual row,female
CN8 = Header 8X2_Female: Header, 8-Pin, Dual row,female
CN9 = Header 15X2_Female: Header, 15-Pin, Dual row,female
CN10 = Header 17X2_Female: Header, 17-Pin, Dual row,female
CN11 CN12 = Header 36X2: Header, 36-Pin, Dual row
LD1 = LED2: as LD5 on sheet MB1312
R31 = Res1: Resistor; Value: 1K
R36 R37 = res1: Resistor; Value: 1K
SB110 SB111 SB119 SB123 SB145 SB146 SB151 SB153 = Circuit Breaker
SB112 SB124 SB126 SB128 SB133 SB136 SB137 SB140 SB144 SB147 SB150 SB155-SB157 SB159 SB168-SB170 SB177 SB179 SB180 SB182 SB188 SB191-SB196 = Circuit Breaker_close: Circuit Breaker

## Sheet ST_LINK_V2-1.SCHDOC: STLINK/V2-1
size A4; DocumentNumber: MB1312; Revision: A-01; SheetNumber: 3; SheetTotal: 6; Project: NUCLEO-LXXXZX
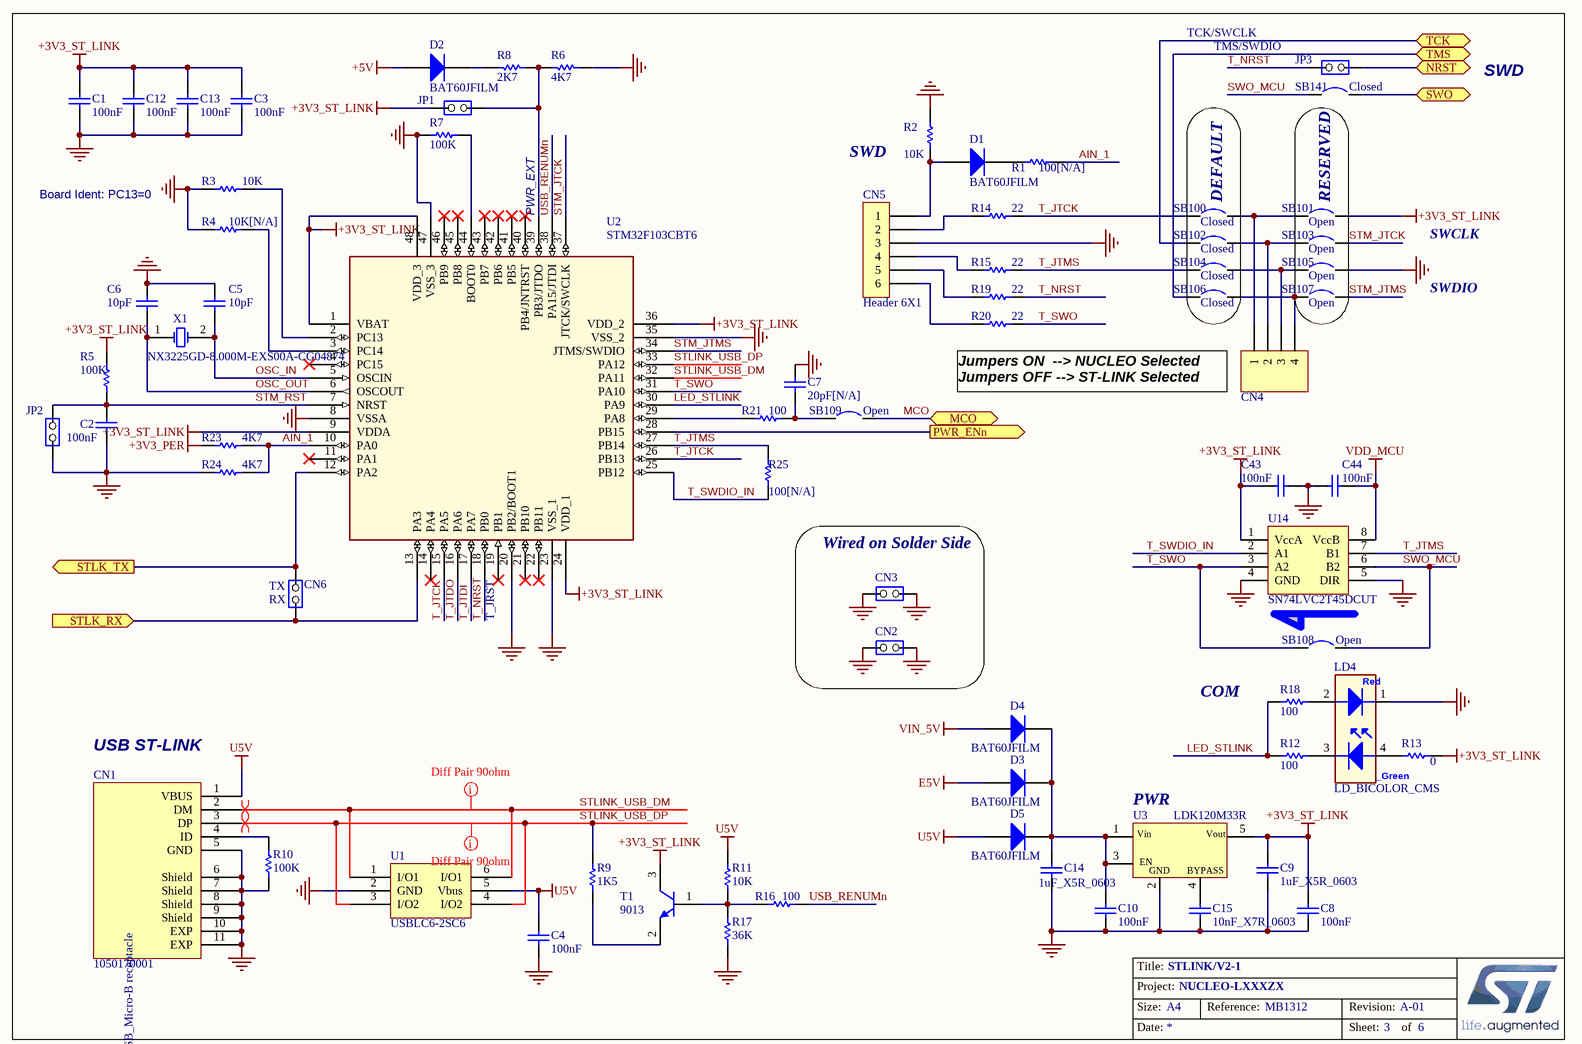
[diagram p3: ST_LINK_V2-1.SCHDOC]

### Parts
C1  100nF  [0603C]
C2  100nF  [0603C]
C3  100nF  [0603C]
C4  100nF  [0603C]
C5  10pF  [0603C]
C6  10pF  [0603C]
C7  20pF[N/A]  [0603C]
C8  100nF  [0603C]
C9  1uF_X5R_0603  [0603C]
C10  100nF  [0603C]
C12  100nF  [0603C]
C13  100nF  [0603C]
C14  1uF_X5R_0603  [0603C]
C15  10nF_X7R_0603  [0603C]
C43  value 100nF  [0603C]  (hidden comment: CC0603KRX7R7BB104)
C44  value 100nF  [0603C]  (hidden comment: CC0603KRX7R7BB104)
CN1  1050170001  [Molex_1050170001]
CN2  (no value)  [HDR_1x2_2R54_V_M]
CN3  (no value)  [HDR_1x2_2R54_V_M]
CN4  Header 4  [HDR_1x4_2R54_V_M]  (value not drawn)
CN5  Header 6X1  [HDR_1x6_2R54_V_M]
CN6  (no value)  [HDR_1x2_2R54_V_M_S]
D1  BAT60JFILM  [SOD-323]
D2  BAT60JFILM  [SOD-323]
D3  BAT60JFILM  [SOD-323]
D4  BAT60JFILM  [SOD-323]
D5  BAT60JFILM  [SOD-323]
JP1  (no value)  [HDR_1x2_2R54_V_M_S]
JP2  (no value)  [HDR_1x2_2R54_V_M_S]
JP3  (no value)  [HDR_1x2_2R54_V_M_S]
LD4  LD_BICOLOR_CMS  [HSMF-A201]
R1  100[N/A]  [0603R]
R2  10K  [0603R]
R3  10K  [0603R]
R4  10K[N/A]  [0603R]
R5  100K  [0603R]
R6  4K7  [0603R]
R7  100K  [0603R]
R8  2K7  [0603R]
R9  1K5  [0603R]
R10  100K  [0603R]
R11  10K  [0603R]
R12  100  [0603R]
R13  0  [0603R]
R14  22  [0603R]
R15  22  [0603R]
R16  100  [0603R]
R17  36K  [0603R]
R18  100  [0603R]
R19  22  [0603R]
R20  22  [0603R]
R21  100  [0603R]
R23  4K7  [0603R]
R24  4K7  [0603R]
R25  100[N/A]  [0603R]
SB100  Closed  [SB_0603]
SB101  Open  [SB_0603]
SB102  Closed  [SB_0603]
SB103  Open  [SB_0603]
SB104  Closed  [SB_0603]
SB105  Open  [SB_0603]
SB106  Closed  [SB_0603]
SB107  Open  [SB_0603]
SB108  Open  [SB_0603]
SB109  Open  [SB_0603]
SB141  Closed  [SB_0603]
T1  9013  [SOT-23]
U1  USBLC6-2SC6  [SOT23-6L]
U2  STM32F103CBT6  [LQFP48_0R5_7x7]
U3  LDK120M33R  [SOT23-5]
U14  SN74LVC2T45DCUT  [USOP8_0R5_2X3R1]
X1  NX3225GD-8.000M-EXS00A-CG04874  [OSC_2SM_3R2x2R5]

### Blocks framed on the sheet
DEFAULT: SB100 SB102 SB104 SB106
RESERVED: SB101 SB103 SB105 SB107
Wired on Solder Side: CN2 CN3

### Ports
MCO, NRST, PWR_ENn (out), STLK_RX (in), STLK_TX (out), SWO, TCK, TMS

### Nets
+3V3_PER: R23.1
+3V3_ST_LINK: C1.2 C3.2 C8.2 C9.1 C12.2 C13.2 C43.2 JP1.1(COMMON) R5.2 R13.2 SB101.2 T1.3(C) U2.1(VBAT) U2.9(VDDA) U2.24(VDD_1) U2.36(VDD_2) U2.48(VDD_3) U3.5(Vout) U14.1(VccA)
+5V: D2.1(A)
E5V: D3.1(A)
GND: C1.1 C2.1 C3.1 C4.1 C5.2 C6.2 C7.2 C8.1 C9.2 C10.1 C12.1 C13.1 C14.1 C15.1 C43.1 C44.2 CN1.5(GND) CN1.6(Shield) CN1.7(Shield) CN1.8(Shield) CN1.9(Shield) CN1.10(EXP) CN1.11(EXP) CN2.1(COMMON) CN2.2(NO) CN3.1(COMMON) CN3.2(NO) CN5.3 JP2.1(COMMON) LD4.1 R2.2 R3.1 R4.1 R6.2 R7.1 R10.2 R17.1 R24.1 SB105.2 U1.2(GND) U2.8(VSSA) U2.20(PB2/BOOT1) U2.23(VSS_1) U2.35(VSS_2) U2.47(VSS_3) U3.2(GND) U14.4(GND) U14.5(DIR)
U5V: C4.2 CN1.1(VBUS) D5.1(A) R11.2 U1.5(Vbus)
VDD_MCU: C44.1 U14.8(VccB)
VIN_5V: D4.1(A)
AIN_1: R1.2 R23.2 R24.2 U2.10(PA0)
LED_STLINK: R12.1 R18.1 U2.30(PA9)
MCO: SB109.1 ; port MCO
NRST: JP3.2(NO) ; port NRST
OSC_IN: C5.1 U2.5(OSCIN) X1.2(OSC2)
OSC_OUT: C6.1 U2.6(OSCOUT) X1.1(OSC1)
PA13: SB106.1 ; port TMS
PA14: SB102.1 ; port TCK
PB3: SB141.2 ; port SWO
STLINK_USB_DM: CN1.2(DM) U1.1(I/O1) U1.6(I/O1) U2.32(PA11)
STLINK_USB_DP: CN1.3(DP) R9.1 U1.3(I/O2) U1.4(I/O2) U2.33(PA12)
STM_JTCK: SB103.2 U2.37(JTCK/SWCLK)
STM_JTMS: SB107.2 U2.34(JTMS/SWDIO)
STM_RST: C2.2 JP2.2(NO) R5.1 U2.7(NRST)
SWO_MCU: SB108.1 SB141.1 U14.6(B2)
T_JTCK: R14.2 SB100.1 U2.15(PA5) U2.26(PB13)
T_JTDI: U2.17(PA7)
T_JTDO: U2.16(PA6)
T_JTMS: R15.2 R25.2 SB104.1 U2.27(PB14) U14.7(B1)
T_NRST: JP3.1(COMMON) R19.2 U2.18(PB0)
T_SWDIO_IN: R25.1 U2.25(PB12) U14.2(A1)
T_SWO: R20.2 SB108.2 U2.31(PA10) U14.3(A2)
USB_RENUMn: R16.2 U2.38(PA15/JTDI)
NetC7_1: C7.1 R21.2 SB109.2
NetC10_2: C10.2 C14.2 D3.2(K) D4.2(K) D5.2(K) U3.1(Vin) U3.3(CE)
NetC15_2: C15.2 U3.4(BYPASS)
NetCN1_4: CN1.4(ID) R10.1
NetCN4_1: CN4.1 SB100.2 SB101.1
NetCN4_2: CN4.2 SB102.2 SB103.1
NetCN4_3: CN4.3 SB104.2 SB105.1
NetCN4_4: CN4.4 SB106.2 SB107.1
NetCN5_1: CN5.1 D1.1(A) R2.1
NetCN5_2: CN5.2 R14.1
NetCN5_4: CN5.4 R15.1
NetCN5_5: CN5.5 R19.1
NetCN5_6: CN5.6 R20.1
NetCN6_1: CN6.1(COMMON) U2.13(PA3) ; port STLK_RX
NetCN6_2: CN6.2(NO) U2.12(PA2) ; port STLK_TX
NetD1_2: D1.2(K) R1.1
NetD2_2: D2.2(K) R8.1
NetJP1_2: JP1.2(NO) R6.1 R8.2 U2.39(PB3/JTDO)
NetLD4_2: LD4.2 R18.2
NetLD4_3: LD4.3 R12.2
NetLD4_4: LD4.4 R13.1
NetR3_2: R3.2 U2.2(PC13)
NetR4_2: R4.2 U2.3(PC14)
NetR7_2: R7.2 U2.44(BOOT0)
NetR9_2: R9.2 T1.2(E)
NetR11_1: R11.1 R16.1 R17.2 T1.1(B)
NetR21_1: R21.1 U2.29(PA8)
NetR26_2: U2.28(PB15) ; port PWR_ENn

Not connected (* = marked no-connect by the designer): U2 4(PC15)* 11(PA1)* 14(PA4)* 19(PB1)* 21(PB10)* 22(PB11)* 40(PB4/JNTRST)* 41(PB5)* 42(PB6)* 43(PB7)* 45(PB8)* 46(PB9)*

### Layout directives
differential pair: (no net found under the mark)
mark named Diff Pair 90ohm: STLINK_USB_DM, STLINK_USB_DP

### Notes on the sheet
- TCK/SWCLK
- TMS/SWDIO
- SWD
- Board Ident: PC13=0
- (near U2) PWR_EXT
- SWCLK
- SWDIO
- Jumpers ON  --> NUCLEO Selected
  Jumpers OFF --> ST-LINK Selected
- (near CN6) TX
- (near CN6) RX
- (near U2) T_JRST
- COM
- (near CN1) USB ST-LINK
- (near U3) PWR

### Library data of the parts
C1-C4 C8 C10 C12 C13 = Capacitor_ST: Capacitor 0402 / 0603 / 0805
C5-C7 = Capacitor_ST: Capacitor 0402 / 0603 / 0805; Value: 100nF
C9 C14 = CAP SMD 0603  X5R 1µF 25V 10%: as C19 on sheet MB1312
C15 = CAP SMD 0603  X7R 10000PF 50V 10%: 0603  X7R 10NF; Order code RS: 2040779; Rated voltage: 50V; Tolerance: 10%
C43 C44 = Cap: Capacitor,100nF,10%,16V,X7R,0603,YAGEO; Ordered by: Subcon
CN1 = 1050170001: Silkscreen: USB
CN2 CN3 JP1-JP3 = JP2
CN4 = Header 4: Header, 4-Pin, Single row
CN5 = Header 6X1: Header, 6-Pin, Single row
CN6 = JP2: Fitted: NO
D1 D3-D5 = BAT60JFILM: Manuf_1: STM; Provided: ST; ECCN_US/EU: EAR99/NEC
D2 = Diode: Default Diode; Code - JEDEC: DO-214-AB; Ordered by: STM; ECCN_US/EU: EAR99/NEC
LD4 = LD_BICOLOR_CMS: Bicolor Led; Manuf_Part_1: HSMF-A201-A00J1; Manuf_1: Avago Technologies; Ref St: xxxxxx; cap_dec: ----
R1 R5 R7 R9 R10 R12-R16 R18-R21 R25 = Resistor_ST: as R27 on sheet MB1312
R2 R3 = Resistor_ST: as R26 on sheet MB1312
R4 R23 R24 = Resistor_ST: Resistor 0402 / 0603 / 0805; Description: Resistor 0402 or 0603 or 0805; Value: 10K; Fitted: NO
R6 R8 R11 R17 = Res1: Resistor; Value: 1K
SB100 SB102 SB104 SB106 SB141 = Circuit Breaker_close: Circuit Breaker
SB101 SB103 SB105 SB107-SB109 = Circuit Breaker
T1 = NPN: NPN Bipolar Transistor; Code - JEDEC: TO-226-AA
U2 = STM32F103CBT6: Medium-density performance line ARM-based 32-bit MCU with 64KB Flash; Manuf_Part_1: STM32F103C8T6; Manuf_1: STM; Ref St: 9175981; Provided: ST; ECCN_US/EU: 3A991A2/NEC
U3 = LDK120M33R: 200 mA low quiescent current very low noise LDO; Manuf_1: STM; Manuf_Part_1: LD3985M33R; Provided: ST; Description: Ultra low drop-low noise BiCMOS voltage, regulators low ESR capacitors compatible; Ref St: 9176161; ECCN_US/EU: EAR99/NEC
U14 = SN74LVC2T45DCUT: Manuf_1: TI; Ordered by: Subcon; ECCN_US/EU: EAR99/NEC
X1 = XTAL: Crystal Oscillator

## Sheet USB.SchDoc: USB
size A4; DocumentNumber: MB1312; Revision: A-01; SheetNumber: 4; SheetTotal: 6; Project: NUCLEO-LXXXZX
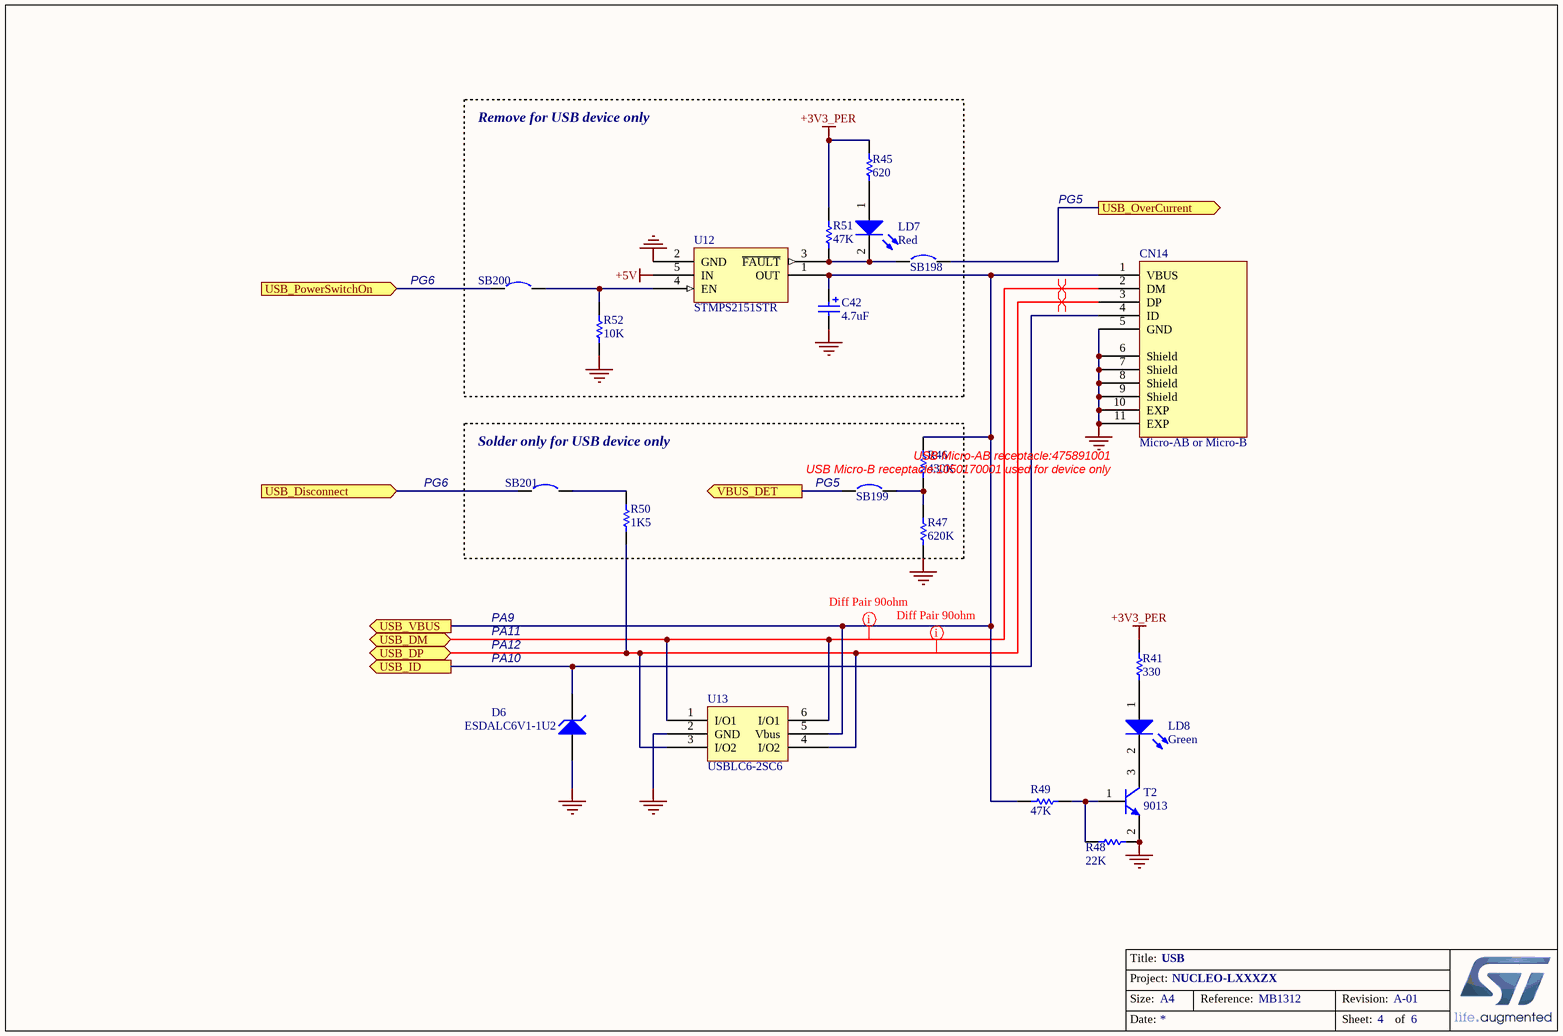
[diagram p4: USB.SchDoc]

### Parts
C42  4.7uF  [TAN-A]
CN14  Micro-AB or Micro-B  [Micro-AB or MicroB]
D6  ESDALC6V1-1U2  [ESDALC6V1-1U2]
LD7  Red  [0603D-R]
LD8  Green  [0603D-G]
R41  330  [0603R]
R45  620  [0603R]
R46  430K  [0603R]
R47  620K  [0603R]
R48  22K  [0603R]
R49  47K  [0603R]
R50  1K5  [0603R]
R51  47K  [0603R]
R52  10K  [0603R]
SB198  Circuit Breaker  [SB_0603]  (value not drawn)
SB199  Circuit Breaker  [SB_0603]  (value not drawn)
SB200  Circuit Breaker  [SB_0603]  (value not drawn)
SB201  Circuit Breaker  [SB_0603]  (value not drawn)
T2  9013  [SOT-23]
U12  STMPS2151STR  [SOT-23-5L]
U13  USBLC6-2SC6  [SOT23-6L]

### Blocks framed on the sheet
Remove for USB device only: C42 LD7 R45 R51 R52 SB198 SB200 U12
Solder only for USB device only: R46 R47 R50 SB199 SB201

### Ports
USB_Disconnect (in), USB_DM (bidir), USB_DP (bidir), USB_ID (out), USB_OverCurrent (out), USB_PowerSwitchOn (in), USB_VBUS (out), VBUS_DET (out)

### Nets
+3V3_PER: R41.2 R45.2 R51.1
+5V: U12.5(IN)
GND: C42.2 CN14.5(GND) CN14.6(Shield) CN14.7(Shield) CN14.8(Shield) CN14.9(Shield) CN14.10(EXP) CN14.11(EXP) D6.2(K) R47.2 R48.1 R52.1 T2.2(E) U12.2(GND) U13.2(GND)
PG6: SB200.1 SB201.1 ; port USB_PowerSwitchOn, port USB_Disconnect
NetC42_1: C42.1 CN14.1(VBUS) R46.1 R49.1 U12.1(OUT) U13.5(Vbus) ; port USB_VBUS
NetCN14_2: CN14.2(DM) U13.1(I/O1) U13.6(I/O1) ; port USB_DM
NetCN14_3: CN14.3(DP) R50.1 U13.3(I/O2) U13.4(I/O2) ; port USB_DP
NetCN14_4: CN14.4(ID) D6.1(A) ; port USB_ID
NetJP4_1: SB198.2 SB199.1 ; port USB_OverCurrent, port VBUS_DET
NetLD7_1: LD7.1(A) R45.1
NetLD7_2: LD7.2(K) R51.2 SB198.1 U12.3(~{FAULT})
NetLD8_1: LD8.1(A) R41.1
NetLD8_2: LD8.2(K) T2.3(C)
NetR46_2: R46.2 R47.1 SB199.2
NetR48_2: R48.2 R49.2 T2.1(B)
NetR50_2: R50.2 SB201.2
NetR52_2: R52.2 SB200.2 U12.4(EN)

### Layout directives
mark named Diff Pair 90ohm: NetCN14_2, NetCN14_3
differential pair: NetCN14_2, NetCN14_3

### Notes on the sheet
- PG5
- PG6
- (near SB199) PG5
- (near CN14) USB Micro-AB receptacle:475891001
- (near CN14) USB Micro-B receptacle:1050170001 used for device only
- PA9
- PA12
- PA11
- PA10

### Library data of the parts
C42 = Cap Pol1: Polarized Capacitor (Radial); Value: 47uF
CN14 = Micro-AB or Micro-B: Silkscreen: USB
D6 = ESDALC6V1-1U2: Zener Diode ESDALC6V1-1U2; Ordered by: STM
LD7 LD8 = LED2: as LD5 on sheet MB1312
R41 R46-R49 R51 = res1: Resistor; Value: 1K
R45 R52 = Res1: Resistor; Value: 1K
R50 = Resistor_ST: as R27 on sheet MB1312
SB198-SB201 = Circuit Breaker: Solder: NO
T2 = NPN: as T1 on sheet ST_LINK_V2-1
U12 = STMPS2141STR

## Sheet SMPS power supply.SchDoc: SMPS power supply
size A3; DocumentNumber: MB1312; Revision: A-01; SheetNumber: 6; SheetTotal: 6; Project: NUCLEO-LXXXZX
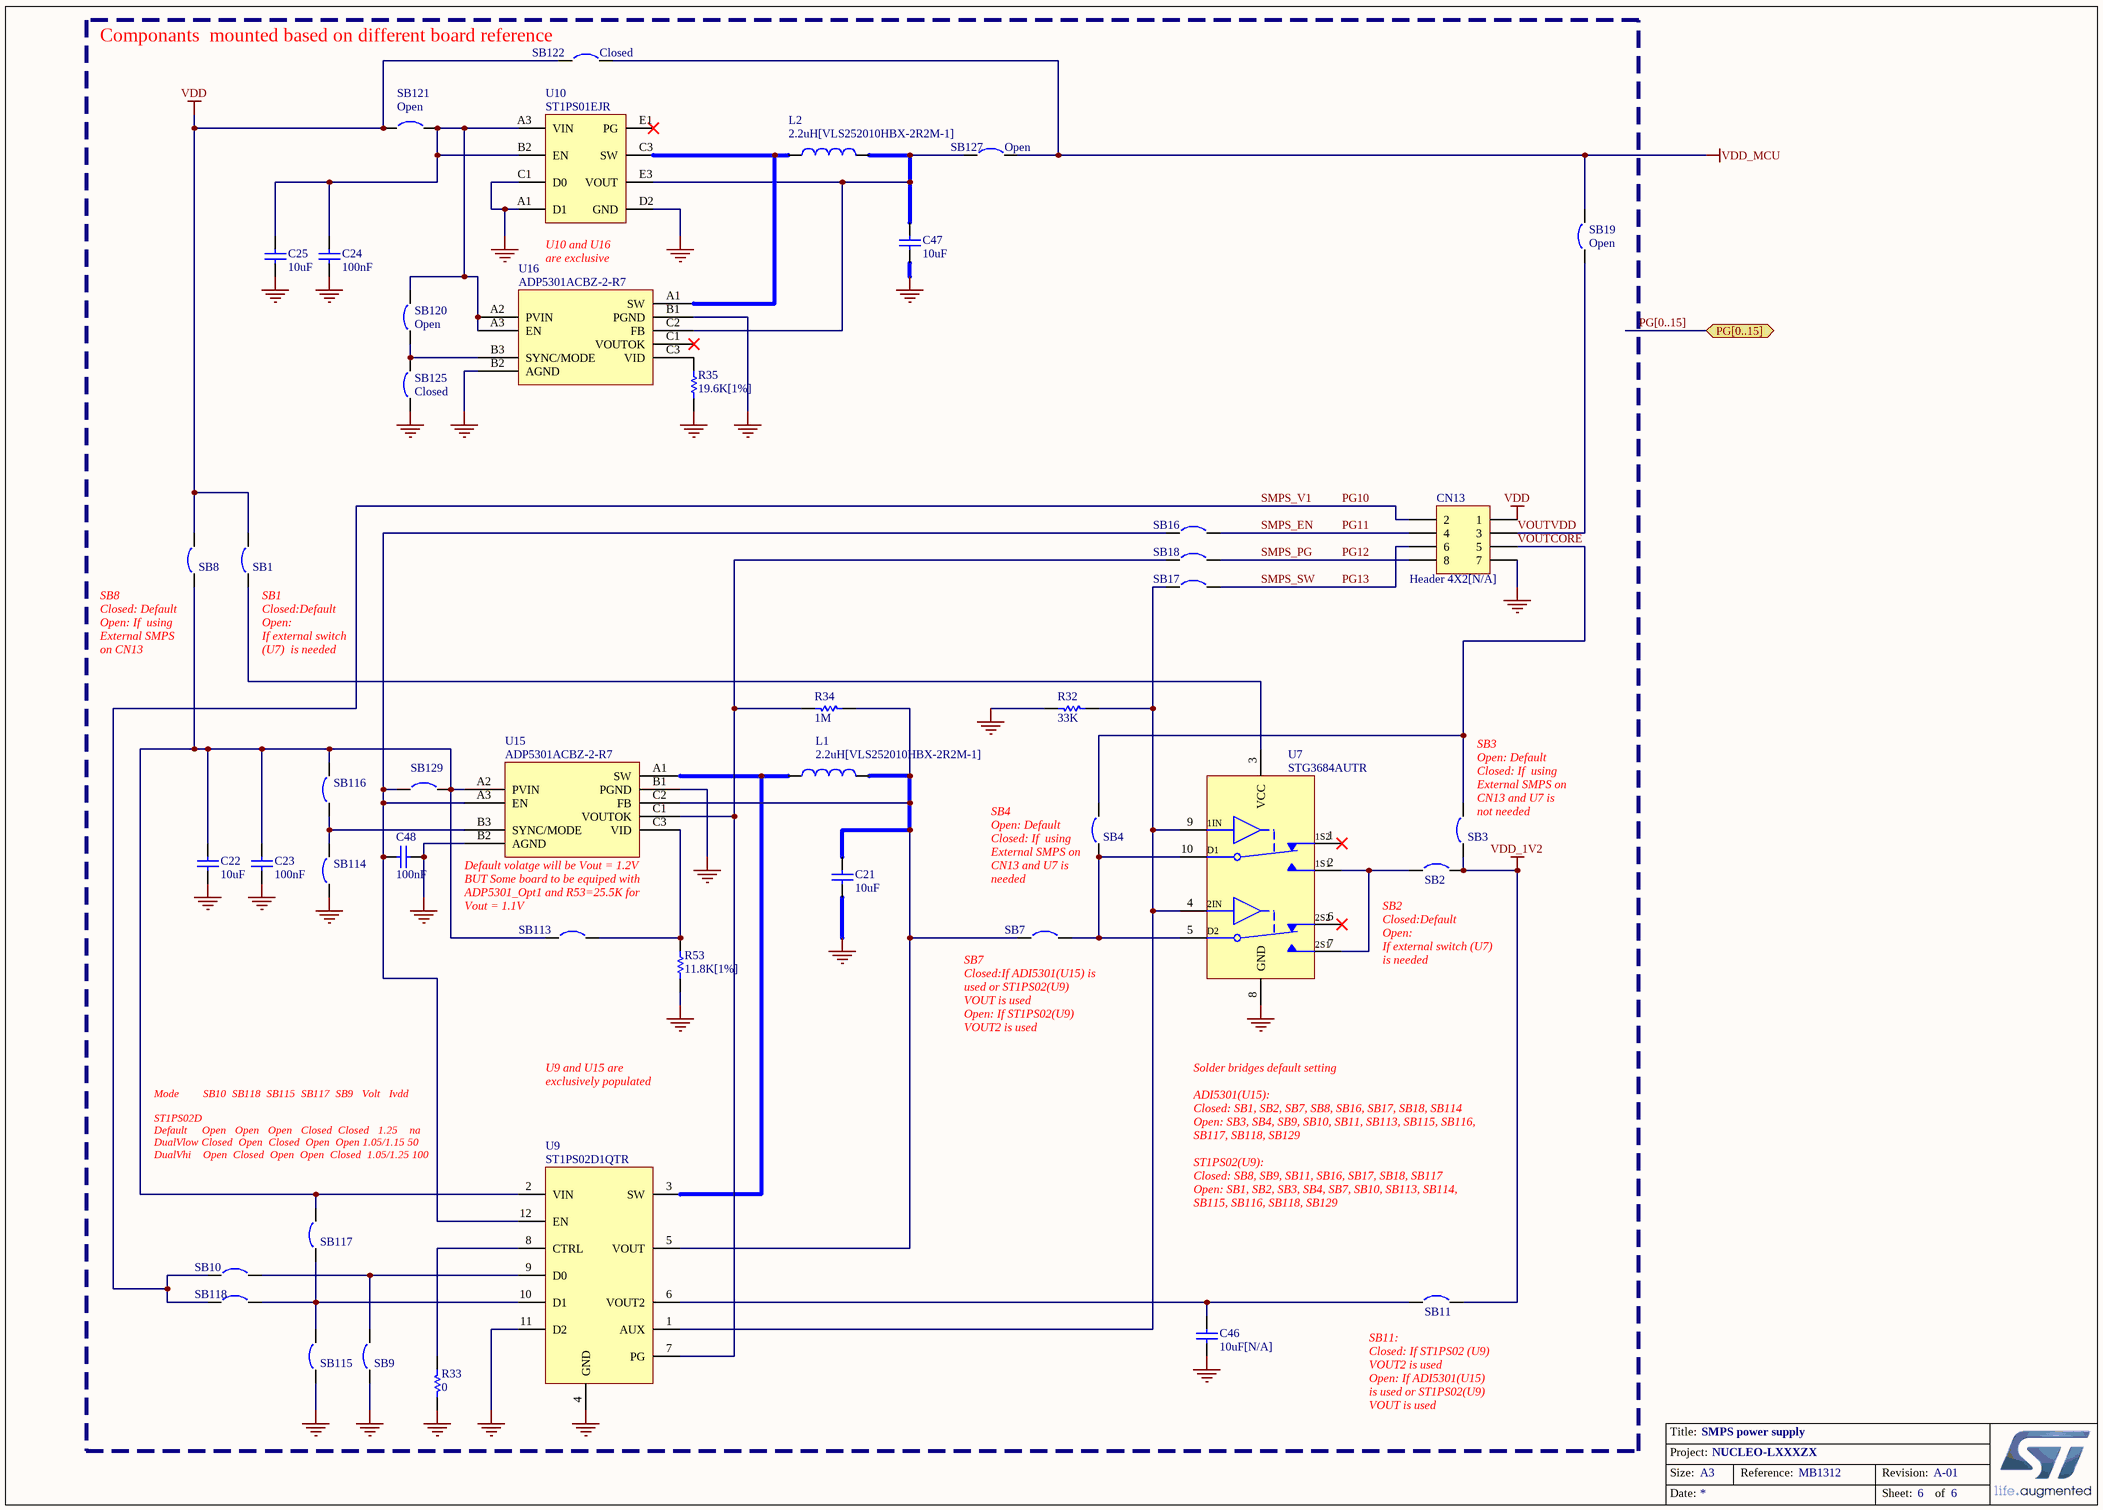
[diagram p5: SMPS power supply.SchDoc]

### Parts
C21  10uF  [0603C]
C22  10uF  [0603C]
C23  100nF  [0603C]
C24  100nF  [0603C]
C25  10uF  [0603C]
C46  10uF[N/A]  [0603C]
C47  10uF  [0603C]
C48  100nF  [0603C]
CN13  Header 4X2[N/A]  [HDR_4x2_2R54_V_M]
L1  2.2uH[VLS252010HBX-2R2M-1]  [L1008_L0805_CPT]
L2  2.2uH[VLS252010HBX-2R2M-1]  [L1008_L0805_CPT]
R32  33K  [0603R]
R33  0  [0603R]
R34  1M  [0603R]
R35  19.6K[1%]  [0603R]
R53  11.8K[1%]  [0603R]
SB1  Circuit Breaker  [SB_0603]  (value not drawn)
SB2  Circuit Breaker  [SB_0603]  (value not drawn)
SB3  Circuit Breaker  [SB_0603]  (value not drawn)
SB4  Circuit Breaker  [SB_0603]  (value not drawn)
SB7  Circuit Breaker  [SB_0603]  (value not drawn)
SB8  Circuit Breaker  [SB_0603]  (value not drawn)
SB9  Circuit Breaker  [SB_0603]  (value not drawn)
SB10  Circuit Breaker  [SB_0603]  (value not drawn)
SB11  Circuit Breaker  [SB_0603]  (value not drawn)
SB16  Circuit Breaker  [SB_0603]  (value not drawn)
SB17  Circuit Breaker  [SB_0603]  (value not drawn)
SB18  Circuit Breaker  [SB_0603]  (value not drawn)
SB19  Open  [SB_0603]
SB113  Open  [SB_0603]  (value not drawn)
SB114  Closed  [SB_0603]  (value not drawn)
SB115  Circuit Breaker  [SB_0603]  (value not drawn)
SB116  Open  [SB_0603]  (value not drawn)
SB117  Circuit Breaker  [SB_0603]  (value not drawn)
SB118  Circuit Breaker  [SB_0603]  (value not drawn)
SB120  Open  [SB_0603]
SB121  Open  [SB_0603]
SB122  Closed  [SB_0603]
SB125  Closed  [SB_0603]
SB127  Open  [SB_0603]
SB129  Open  [SB_0603]  (value not drawn)
U7  STG3684AUTR  [QFN40P180X140X55-10N]
U9  ST1PS02D1QTR  [QFN0P170X200X55-12N]
U10  ST1PS01EJR  [Flipchip8]
U15  ADP5301ACBZ-2-R7  [WLCSP-9ball]
U16  ADP5301ACBZ-2-R7  [WLCSP-9ball]

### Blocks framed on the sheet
Componants  mounted based on different board reference: C21-C25 C46-C48 CN13 L1 L2 R32-R35 R53 SB1-SB4 SB7-SB11 SB16-SB19 SB113-SB118 SB120-SB122 SB125 SB127 SB129 U7 U9 U10 U15 U16

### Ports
PG[0..15] (bidir)

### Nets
GND: C21.1 C22.1 C23.2 C24.2 C25.1 C46.1 C47.1 C48.2 CN13.7 R32.2 R33.1 R35.1 R53.1 SB9.1 SB114.1 SB115.1 SB125.1 U7.8(GND) U9.4(GND) U9.11(D2) U10.A1(D1) U10.C1(D0) U10.D2(GND) U15.B1(PGND) U15.B2(AGND) U16.B1(PGND) U16.B2(AGND)
VDD: CN13.1 SB1.2 SB8.2 SB121.1 SB122.1
VDD_1V2: SB2.2 SB3.1 SB11.2
VDD_MCU: SB19.2 SB122.2 SB127.2
PG10: CN13.2 SB10.1 SB118.1  [also labelled SMPS_V1]
PG11: CN13.4 SB16.2  [also labelled SMPS_EN]
PG12: CN13.8 SB18.2  [also labelled SMPS_PG]
PG13: CN13.6 SB17.2  [also labelled SMPS_SW]
VOUTCORE: CN13.5 SB3.2 SB4.2
VOUTVDD: CN13.3 SB19.1
NetC21_2: C21.2 L1.2 R34.1 SB7.1 U9.5(VOUT) U15.C2(FB)
NetC22_2: C22.2 C23.1 SB8.1 SB113.1 SB116.2 SB117.2 SB129.2 U9.2(VIN) U15.A2(PVIN)
NetC24_1: C24.1 C25.2 SB120.2 SB121.2 U10.A3(VIN) U10.B2(EN) U16.A2(PVIN) U16.A3(EN)
NetC46_2: C46.2 SB11.1 U9.6(VOUT2)
NetC47_2: C47.2 L2.2 SB127.1 U10.E3(VOUT) U16.C2(FB)
NetC48_1: C48.1 SB16.1 SB129.1 U9.12(EN) U15.A3(EN)
NetL1_1: L1.1 U9.3(SW) U15.A1(SW)
NetL2_1: L2.1 U10.C3(SW) U16.A1(SW)
NetR32_1: R32.1 SB17.1 U7.4(2IN) U7.9(1IN) U9.1(AUX)
NetR33_2: R33.2 U9.8(CTRL)
NetR34_2: R34.2 SB18.1 U9.7(PG) U15.C1(VOUTOK)
NetR35_2: R35.2 U16.C3(VID)
NetR53_2: R53.2 SB113.2 U15.C3(VID)
NetSB1_1: SB1.1 U7.3(VCC)
NetSB2_1: SB2.1 U7.2(1S1) U7.7(2S1)
NetSB4_1: SB4.1 SB7.2 U7.5(D2) U7.10(D1)
NetSB9_2: SB9.2 SB10.2 U9.9(D0)
NetSB114_2: SB114.2 SB116.1 U15.B3(SYNC/MODE)
NetSB115_2: SB115.2 SB117.1 SB118.2 U9.10(D1)
NetSB120_1: SB120.1 SB125.2 U16.B3(SYNC/MODE)

Not connected (* = marked no-connect by the designer): U7 1(1S2)* 6(2S2)*; U10 E1(PG)*; U16 C1(VOUTOK)*

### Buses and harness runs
bus PG[0..15] = port PG[0..15]

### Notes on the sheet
- U10 and U16 are exclusive
- (near SB1) SB1
  Closed:Default
  Open:
  If external switch (U7)  is needed
- (near SB8) SB8
  Closed: Default
  Open: If  using External SMPS on CN13
- (near SB3) SB3
  Open: Default
  Closed: If  using External SMPS on CN13 and U7 is not needed
- Default volatge will be Vout = 1.2V
  BUT Some board to be equiped with ADP5301_Opt1 and R53=25.5K for Vout = 1.1V
- (near SB4) SB4
  Open: Default
  Closed: If  using External SMPS on CN13 and U7 is needed
- (near SB2) SB2
  Closed:Default
  Open:
  If external switch (U7)  is needed
- U9 and U15 are exclusively populated
- (near SB7) SB7
  Closed:If ADI5301(U15) is used or ST1PS02(U9) VOUT is used
  Open: If ST1PS02(U9) VOUT2 is used
- (near SB117) Mode        SB10  SB118  SB115  SB117  SB9   Volt   Ivdd
  ST1PS02D
  Default     Open   Open   Open   Closed  Closed   1.25    na
  DualVlow Closed  Open  Closed  Open  Open 1.05/1.15 50
  DualVhi    Open  Closed  Open  Open  Closed  1.05/1.25 100
- Solder bridges default setting
  ADI5301(U15):
  Closed: SB1, SB2, SB7, SB8, SB16, SB17, SB18, SB114
  Open: SB3, SB4, SB9, SB10, SB11, SB113, SB115, SB116, SB117, SB118, SB129
  ST1PS02(U9):
  Closed: SB8, SB9, SB11, SB16, SB17, SB18, SB117
  Open: SB1, SB2, SB3, SB4, SB7, SB10, SB113, SB114, SB115, SB116, SB118, SB129
- (near SB11) SB11:
  Closed: If ST1PS02 (U9) VOUT2 is used
  Open: If ADI5301(U15) is used or ST1PS02(U9) VOUT is used

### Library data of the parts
C21 C22 C25 C46 C47 = Cap: Capacitor; Value: 10nF
C23 C24 C48 = CAP_CC0603KRX7R9BB104: Capacitor SMD 0603 100000pF X7R 50V +/-10%; Manufacturer: YAGEO; Order code RS: 669-8767; Tolerance: 10%; Fitted: Yes
CN13 = Header 4X2_CN: Header, 4-Pin, Dual row
L1 L2 = Inductor: Manuf_1: TDK; Value: 2.2uH; Ordered by: Subcon; ECCN_US/EU: NA
R32-R34 = Res1: Resistor; Value: 1K
R35 R53 = res1: Resistor; Value: 1K
SB1-SB4 SB7-SB11 SB16-SB18 SB115 SB117 SB118 = Circuit Breaker: Solder: NO
SB19 SB113 SB116 SB120 SB121 SB127 SB129 = Circuit Breaker
SB114 SB122 SB125 = Circuit Breaker_close: Circuit Breaker
U7 = STG3684AUTR: Low voltage 0.5 O max dual SPDT switch with break-before-make; Manufacturer: ST; Order code RS: ...; Fitted: Yes
U9 = ST1PS022D1QTR: 400mA Nano-Quiescent?Synchronous step-down converter  with voltage selection, power good, Aux Switch; Manufacturer: STMicroelectronics; Order code RS: ...
U10 = ST1PS01FJR: 400mA Nano-Quiescent?Synchronous step-down converter  with voltage selection and power good; Manufacturer: STMicroelectronics
U15 U16 = ADP5301: UL Step down regulator

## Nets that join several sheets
+3V3: MB1312 (JP5.1 SB5.1 SB6.2), Connectors (CN8.7 CN11.16 SB111.1)
+3V3_PER: MB1312 (SB5.2), Connectors (SB110.1 U8.5), ST_LINK_V2-1 (R23.1), USB (R41.2 R45.2 R51.1)
+5V: MB1312 (9 pins), Connectors (CN8.9 CN11.18), ST_LINK_V2-1 (D2.1), USB (U12.5)
AGND: STM32L_144 (7 pins), Connectors (C45.2 CN10.3 CN12.32)
AVDD: STM32L_144 (5 pins), Connectors (CN10.1)
E5V: MB1312 (JP6.2), Connectors (CN11.6), ST_LINK_V2-1 (D3.1)
GND: MB1312 (14 pins), STM32L_144 (40 pins), Connectors (27 pins), ST_LINK_V2-1 (48 pins), USB (15 pins), SMPS power supply (27 pins)
U5V: MB1312 (6 pins), Connectors (CN12.8), ST_LINK_V2-1 (5 pins)
VBAT: STM32L_144 (C60.1 SB154.2 U11.6), Connectors (CN11.33)
VDD: MB1312 (JP5.2), STM32L_144 (8 pins), Connectors (CN11.5), SMPS power supply (5 pins)
VDD_1V2: STM32L_144 (C39.2 C55.2 SB15.2 SB139.2), SMPS power supply (SB2.2 SB3.1 SB11.2)
VDD_MCU: STM32L_144 (24 pins), Connectors (SB112.1), ST_LINK_V2-1 (C44.1 U14.8), SMPS power supply (SB19.2 SB122.2 SB127.2)
VIN: MB1312 (C18.1 U5.3), Connectors (CN8.15 CN11.24)
VIN_5V: MB1312 (C17.1 JP6.8 U5.2 U5.4), ST_LINK_V2-1 (D4.1)
VREF+: STM32L_144 (C56.1 C57.1 SB149.2 U11.32), Connectors (C45.1 SB119.1)
MCO: STM32L_144 (SB148.2), ST_LINK_V2-1 (SB109.1)
NetC42_1: STM32L_144 (R54.1), USB (6 pins)
NetCN6_1: STM32L_144 (SB131.2), ST_LINK_V2-1 (CN6.1 U2.13)
NetCN6_2: STM32L_144 (SB130.2), ST_LINK_V2-1 (CN6.2 U2.12)
NetCN14_2: STM32L_144 (SB142.1), USB (CN14.2 U13.1 U13.6)
NetCN14_3: STM32L_144 (SB143.1), USB (CN14.3 R50.1 U13.3 U13.4)
NetCN14_4: STM32L_144 (SB134.1), USB (CN14.4 D6.1)
NetJP4_1: STM32L_144 (JP4.1), USB (SB198.2 SB199.1)
NetR26_2: MB1312 (R26.2 U4.3), ST_LINK_V2-1 (U2.28)
NRST: STM32L_144 (B2.2 B2.3 C41.2 U11.25), Connectors (CN8.5 CN11.14), ST_LINK_V2-1 (JP3.2)
PA0: STM32L_144 (SB178.2 U11.34), Connectors (CN11.28 SB179.1)
PA1: STM32L_144 (U11.35), Connectors (CN10.11 CN11.30)
PA2: STM32L_144 (U11.36), Connectors (CN12.35 SB150.1)
PA3: STM32L_144 (U11.37), Connectors (CN9.1 CN12.37)
PA4: STM32L_144 (U11.40), Connectors (CN11.32 SB126.1 SB133.1)
PA5: STM32L_144 (U11.41), Connectors (CN7.10 CN12.11 SB123.2)
PA6: STM32L_144 (U11.42), Connectors (CN7.12 CN12.13)
PA7: STM32L_144 (U11.43), Connectors (CN7.14 CN12.15)
PA8: STM32L_144 (TP1.1 U11.100), Connectors (CN12.23)
PA9: STM32L_144 (SB135.2 U11.101), Connectors (CN12.21)
PA10: STM32L_144 (SB134.2 U11.102), Connectors (CN12.33)
PA11: STM32L_144 (SB142.2 U11.103), Connectors (CN12.14)
PA12: STM32L_144 (SB143.2 U11.104), Connectors (CN12.12)
PA13: STM32L_144 (U11.105), Connectors (CN11.13), ST_LINK_V2-1 (SB106.1)
PA14: STM32L_144 (U11.109), Connectors (CN11.15), ST_LINK_V2-1 (SB102.1)
PA15: STM32L_144 (U11.110), Connectors (CN11.17)
PB0: STM32L_144 (U11.46), Connectors (SB144.2 SB159.1 SB182.1)
PB1: STM32L_144 (U11.47), Connectors (CN10.7 CN12.24)
PB2: STM32L_144 (U11.48), Connectors (CN9.13 CN12.22)
PB3: STM32L_144 (SB161.2 SB162.2), Connectors (CN7.15 CN12.31), ST_LINK_V2-1 (SB141.2)
PB4: STM32L_144 (SB163.2 SB164.2), Connectors (CN12.27 SB128.1 SB140.1)
PB5: STM32L_144 (SB165.2 SB176.2), Connectors (CN7.13 CN12.29)
PB6: STM32L_144 (SB174.2 SB175.2), Connectors (CN9.15 CN12.17)
PB7: STM32L_144 (R30.1 SB172.2 SB173.2), Connectors (CN11.21)
PB8: STM32L_144 (SB181.2 SB184.2), Connectors (CN7.2 CN12.3 SB153.2)
PB9: STM32L_144 (SB185.2 SB186.2), Connectors (CN7.4 CN12.5 SB151.2)
PB10: STM32L_144 (U11.69), Connectors (CN12.25 SB155.1 SB188.2)
PB11: STM32L_144 (SB138.2), Connectors (CN10.34 CN12.18)
PB12: STM32L_144 (U11.73), Connectors (CN7.7 CN12.16)
PB13: STM32L_144 (U11.74), Connectors (CN7.5 CN12.30)
PB14: STM32L_144 (SB132.1 U11.75), Connectors (CN12.28)
PB15: STM32L_144 (U11.76), Connectors (CN7.3 CN12.26)
PC0: STM32L_144 (U11.26), Connectors (CN9.3 CN11.38)
PC1: STM32L_144 (U11.27), Connectors (CN9.7 CN11.36)
PC2: STM32L_144 (U11.28), Connectors (CN10.9 CN11.35)
PC3: STM32L_144 (U11.29), Connectors (CN9.5 CN11.37)
PC4: STM32L_144 (U11.44), Connectors (CN9.9 CN12.34 SB151.1)
PC5: STM32L_144 (U11.45), Connectors (CN9.11 CN12.6 SB153.1)
PC6: STM32L_144 (U11.96), Connectors (CN7.1 CN12.4)
PC7: STM32L_144 (U11.97), Connectors (CN12.19 SB124.1)
PC8: STM32L_144 (U11.98), Connectors (CN8.2 SB137.1)
PC9: STM32L_144 (U11.99), Connectors (CN8.4 SB136.1)
PC10: STM32L_144 (U11.111), Connectors (CN8.6 CN11.1)
PC11: STM32L_144 (U11.112), Connectors (CN8.8 CN11.2)
PC12: STM32L_144 (U11.113), Connectors (CN8.10 CN11.3)
PC13: STM32L_144 (SB197.1 U11.7), Connectors (CN11.23)
PC14: STM32L_144 (R39.2 U11.8), Connectors (SB145.1)
PC15: STM32L_144 (R40.2 U11.9), Connectors (SB146.1)
PD0: STM32L_144 (U11.114), Connectors (CN9.25 CN11.57)
PD1: STM32L_144 (U11.115), Connectors (CN9.27 CN11.55)
PD2: STM32L_144 (U11.116), Connectors (CN8.12 CN11.4)
PD3: STM32L_144 (U11.117), Connectors (CN9.10 CN11.40)
PD4: STM32L_144 (U11.118), Connectors (CN9.8 CN11.39)
PD5: STM32L_144 (U11.119), Connectors (CN9.6 CN11.41)
PD6: STM32L_144 (U11.122), Connectors (CN9.4 CN11.43)
PD7: STM32L_144 (U11.123), Connectors (CN9.2 CN11.45)
PD8: STM32L_144 (U11.77), Connectors (CN10.14 CN12.10)
PD9: STM32L_144 (U11.78), Connectors (CN10.16 CN11.69)
PD10: STM32L_144 (U11.79), Connectors (CN12.65)
PD11: STM32L_144 (U11.80), Connectors (CN12.45)
PD12: STM32L_144 (U11.81), Connectors (CN12.43)
PD13: STM32L_144 (U11.82), Connectors (CN12.41)
PD14: STM32L_144 (U11.85), Connectors (CN7.16 CN12.46)
PD15: STM32L_144 (U11.86), Connectors (CN7.18 CN12.48)
PE0: STM32L_144 (SB187.2 SB190.1), Connectors (CN10.33 CN12.64)
PE1: STM32L_144 (SB14.1 SB189.1), Connectors (CN11.61)
PE2: STM32L_144 (U11.1), Connectors (CN9.14 CN11.46)
PE3: STM32L_144 (U11.2), Connectors (CN9.22 CN11.47)
PE4: STM32L_144 (U11.3), Connectors (CN9.16 CN11.48)
PE5: STM32L_144 (U11.4), Connectors (CN9.18 CN11.50)
PE6: STM32L_144 (U11.5), Connectors (CN9.20 CN11.62)
PE7: STM32L_144 (U11.58), Connectors (CN10.20 CN12.44)
PE8: STM32L_144 (U11.59), Connectors (CN10.18 CN12.40)
PE9: STM32L_144 (U11.60), Connectors (CN10.4 CN12.52)
PE10: STM32L_144 (U11.63), Connectors (CN10.24 CN12.47)
PE11: STM32L_144 (U11.64), Connectors (CN10.6 CN12.56)
PE12: STM32L_144 (U11.65), Connectors (CN12.49 SB168.1 SB169.2)
PE13: STM32L_144 (U11.66), Connectors (CN10.10 CN12.55)
PE14: STM32L_144 (U11.67), Connectors (CN12.51 SB170.1 SB177.2)
PE15: STM32L_144 (U11.68), Connectors (CN12.53 SB157.1 SB180.2)
PF0: STM32L_144 (U11.10), Connectors (CN9.21 CN11.53)
PF1: STM32L_144 (U11.11), Connectors (CN9.19 CN11.51)
PF2: STM32L_144 (U11.12), Connectors (CN9.17 CN11.52)
PF3: STM32L_144 (U11.13), Connectors (CN8.14 CN12.58)
PF4: STM32L_144 (U11.14), Connectors (CN12.38)
PF5: STM32L_144 (U11.15), Connectors (CN8.16 CN12.36)
PF6: STM32L_144 (U11.18), Connectors (CN11.9)
PF7: STM32L_144 (U11.19), Connectors (CN9.26 CN11.11)
PF8: STM32L_144 (U11.20), Connectors (CN9.24 CN11.54)
PF9: STM32L_144 (U11.21), Connectors (CN9.28 CN11.56)
PF10: STM32L_144 (U11.22), Connectors (CN12.42)
PF11: STM32L_144 (U11.49), Connectors (CN12.62)
PF12: STM32L_144 (U11.50), Connectors (CN7.20 CN12.59)
PF13: STM32L_144 (U11.53), Connectors (CN10.2 CN12.57)
PF14: STM32L_144 (U11.54), Connectors (CN10.8 CN12.50)
PF15: STM32L_144 (U11.55), Connectors (CN10.12 CN12.60)
PG0: STM32L_144 (U11.56), Connectors (CN9.29 CN11.59)
PG1: STM32L_144 (U11.57), Connectors (CN9.30 CN11.58)
PG2: STM32L_144 (U11.87), Connectors (CN11.42)
PG3: STM32L_144 (U11.88), Connectors (CN11.44)
PG4: STM32L_144 (U11.89), Connectors (CN12.69)
PG5: STM32L_144 (JP4.2 U11.90), Connectors (CN12.68)
PG6: STM32L_144 (U11.91), Connectors (CN12.70), USB (SB200.1 SB201.1)
PG7: STM32L_144 (SB131.1 U11.92), Connectors (SB195.1)
PG8: STM32L_144 (SB130.1 U11.93), Connectors (SB193.2)
PG9: STM32L_144 (U11.124), Connectors (CN11.63)
PG10: STM32L_144 (U11.125), Connectors (SB192.2), SMPS power supply (CN13.2 SB10.1 SB118.1)
PG11: STM32L_144 (U11.126), Connectors (SB196.2), SMPS power supply (CN13.4 SB16.2)
PG12: STM32L_144 (U11.127), Connectors (SB191.1), SMPS power supply (CN13.8 SB18.2)
PG13: STM32L_144 (U11.128), Connectors (SB194.2), SMPS power supply (CN13.6 SB17.2)
PG14: STM32L_144 (U11.129), Connectors (CN12.61)
PG15: STM32L_144 (SB160.2), Connectors (CN11.64)
PH0: STM32L_144 (SB12.2 SB148.1 U11.23), Connectors (SB147.1)
PH1: STM32L_144 (SB13.2 U11.24), Connectors (SB156.1)
PH3-BOOT0: STM32L_144 (R38.1 SB171.2 SB183.2), Connectors (CN11.7)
